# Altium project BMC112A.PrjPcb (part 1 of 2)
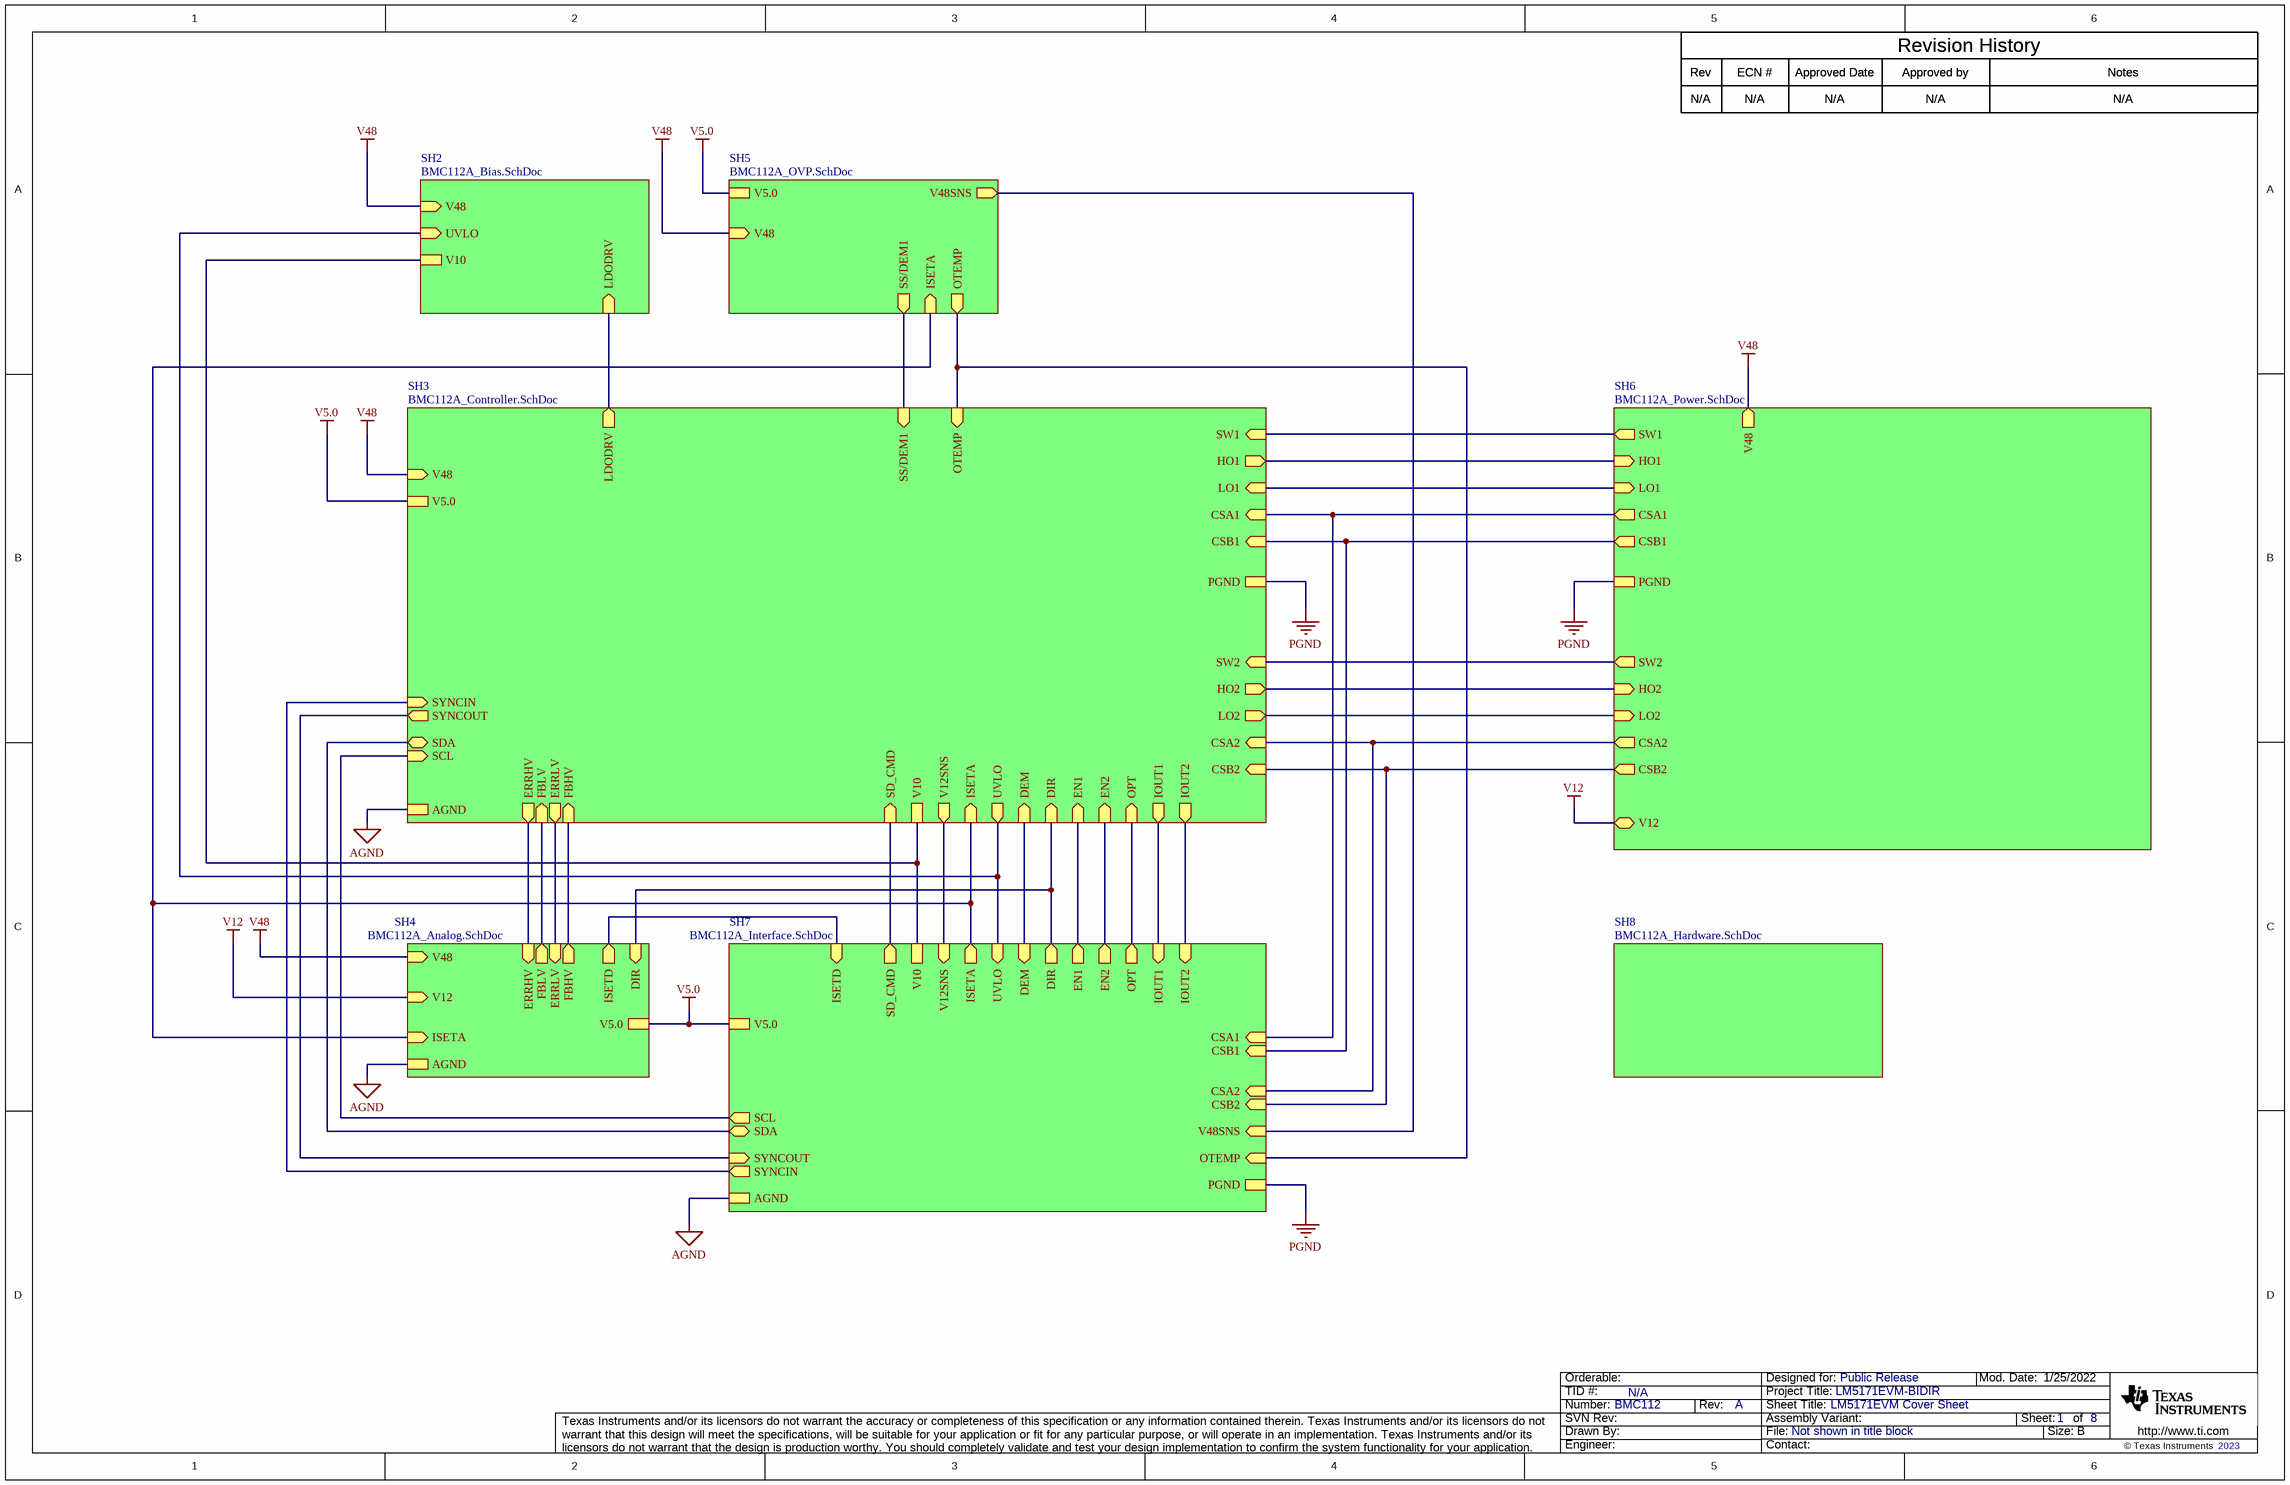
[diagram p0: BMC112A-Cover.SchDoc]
TID: N/A; SCH_Rev: A; PRJ_Title: LM5171EVM-BIDIR; PRJ_Number: BMC112; PRJ_Customer: Public Release; PCB_Rev: A; CopyrightYear: 2023
8 sheets, 367 parts. Net scope: hierarchical (ports join the sheet entries above them; power ports are global).
Board file: BMC112A.PcbDoc
Sheets:
  BMC112A-Cover.SchDoc
    SH2 = BMC112A_Bias.SchDoc
    SH5 = BMC112A_OVP.SchDoc
    SH3 = BMC112A_Controller.SchDoc
    SH6 = BMC112A_Power.SchDoc
    SH7 = BMC112A_Interface.SchDoc
    SH4 = BMC112A_Analog.SchDoc
    SH8 = BMC112A_Hardware.SchDoc

## Sheet BMC112A-Cover.SchDoc: LM5171EVM Cover Sheet
size 431 x 279 mm; Date: Not shown in title block; ApprovedBy: Not shown in title block; CheckedBy: Not shown in title block; Author: Not shown in title block; CompanyName: Not shown in title block; Engineer: Not shown in title block; Organization: Not shown in title block; Address1: Not shown in title block; Address2: Not shown in title block; Address3: Not shown in title block; Address4: Not shown in title block; DocumentNumber: 1; Revision: Use project parameter SCH_Rev; SheetNumber: 1; SheetTotal: 8; PageSetup: Record=PageOptions¦CenterHorizontal=True¦CenterVertical=True¦PrintScale=1.00¦XCorrection=1.00¦YCorrection=1.00¦PrintKind=0¦BorderSize=5000000¦LeftOffset=0¦BottomOffset=0¦Orientation=2¦PaperLength=1000¦PaperWidth=1000¦Scale=100¦PaperSource=15¦PrintQuality=600¦MediaType=1¦DitherType=10¦PaperKind=Letter¦PrintScaleMode=1

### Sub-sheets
SH2 = BMC112A_Bias.SchDoc: LDODRV (in), UVLO (in), V10, V48 (in)
SH3 = BMC112A_Controller.SchDoc: HO2 (out), CSA1 (in), CSB2 (in), CSA2 (in), IOUT1 (out), ERRLV (out), UVLO (out), V12SNS (out), SYNCIN (in), SYNCOUT (out), OTEMP (in), SW1 (in), FBHV (in), LO2 (out), OPT (in), FBLV (in), CSB1 (in), SW2 (in), ISETA (in), V10, EN1 (in), DIR (in), HO1 (out), ERRHV (out), LO1 (in), SDA (bidir), SD_CMD (in), IOUT2 (out), SS/DEM1 (in), EN2 (in), DEM (in), V48 (in), SCL (in), AGND, PGND, LDODRV (out), V5.0
SH4 = BMC112A_Analog.SchDoc: AGND, ISETA (in), ERRHV (in), DIR (in), V5.0, ERRLV (in), FBLV (out), ISETD (out), FBHV (out), V48 (in), V12 (in)
SH5 = BMC112A_OVP.SchDoc: V5.0, SS/DEM1 (out), ISETA (in), V48SNS (out), V48 (in), OTEMP (out)
SH6 = BMC112A_Power.SchDoc: CSA1 (out), CSA2 (out), LO1 (in), HO1 (in), CSB1 (out), SW1 (out), LO2 (in), CSB2 (out), SW2 (out), V12 (bidir), PGND, V48 (out), HO2 (in)
SH7 = BMC112A_Interface.SchDoc: IOUT2 (in), CSA1 (in), V48SNS (in), ISETD (in), V10, UVLO (in), SDA (bidir), DIR (out), DEM (in), SCL (out), IOUT1 (in), PGND, EN1 (out), V5.0, EN2 (out), SYNCOUT (in), SYNCIN (out), V12SNS (in), ISETA (out), SD_CMD (out), CSB2 (in), AGND, CSA2 (in), CSB1 (in), OPT (out), OTEMP (in)
SH8 = BMC112A_Hardware.SchDoc: no entries

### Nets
AGND: sheet SH3/AGND, sheet SH7/AGND, sheet SH4/AGND
PGND: sheet SH3/PGND, sheet SH6/PGND, sheet SH7/PGND
V5.0: sheet SH5/V5.0, sheet SH3/V5.0, sheet SH7/V5.0, sheet SH4/V5.0
V10: sheet SH2/V10, sheet SH3/V10, sheet SH7/V10
V12: sheet SH6/V12, sheet SH4/V12
V48: sheet SH2/V48, sheet SH5/V48, sheet SH3/V48, sheet SH6/V48, sheet SH4/V48
CSA1: sheet SH3/CSA1, sheet SH6/CSA1, sheet SH7/CSA1
CSA2: sheet SH3/CSA2, sheet SH6/CSA2, sheet SH7/CSA2
CSB1: sheet SH3/CSB1, sheet SH6/CSB1, sheet SH7/CSB1
CSB2: sheet SH3/CSB2, sheet SH6/CSB2, sheet SH7/CSB2
DEM: sheet SH3/DEM, sheet SH7/DEM
DIR: sheet SH3/DIR, sheet SH7/DIR, sheet SH4/DIR
EN1: sheet SH3/EN1, sheet SH7/EN1
EN2: sheet SH3/EN2, sheet SH7/EN2
ERRHV: sheet SH3/ERRHV, sheet SH4/ERRHV
ERRLV: sheet SH3/ERRLV, sheet SH4/ERRLV
FBHV: sheet SH3/FBHV, sheet SH4/FBHV
FBLV: sheet SH3/FBLV, sheet SH4/FBLV
HO1: sheet SH3/HO1, sheet SH6/HO1
HO2: sheet SH3/HO2, sheet SH6/HO2
IOUT1: sheet SH3/IOUT1, sheet SH7/IOUT1
IOUT2: sheet SH3/IOUT2, sheet SH7/IOUT2
ISETA: sheet SH5/ISETA, sheet SH3/ISETA, sheet SH7/ISETA, sheet SH4/ISETA
ISETD: sheet SH7/ISETD, sheet SH4/ISETD
LDODRV: sheet SH2/LDODRV, sheet SH3/LDODRV
LO1: sheet SH3/LO1, sheet SH6/LO1
LO2: sheet SH3/LO2, sheet SH6/LO2
OPT: sheet SH3/OPT, sheet SH7/OPT
OTEMP: sheet SH5/OTEMP, sheet SH3/OTEMP, sheet SH7/OTEMP
SCL: sheet SH3/SCL, sheet SH7/SCL
SD_CMD: sheet SH3/SD_CMD, sheet SH7/SD_CMD
SDA: sheet SH3/SDA, sheet SH7/SDA
SS/DEM1: sheet SH5/SS/DEM1, sheet SH3/SS/DEM1
SW1: sheet SH3/SW1, sheet SH6/SW1
SW2: sheet SH3/SW2, sheet SH6/SW2
SYNCIN: sheet SH3/SYNCIN, sheet SH7/SYNCIN
SYNCOUT: sheet SH3/SYNCOUT, sheet SH7/SYNCOUT
UVLO: sheet SH2/UVLO, sheet SH3/UVLO, sheet SH7/UVLO
V12SNS: sheet SH3/V12SNS, sheet SH7/V12SNS
V48SNS: sheet SH5/V48SNS, sheet SH7/V48SNS

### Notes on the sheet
- Rev
- N/A
- ECN #
- Approved Date
- Approved by
- Revision History
- Notes

## Sheet BMC112A_Bias.SchDoc: LM5171 EVM Auz Bias
size 431 x 279 mm; Date: Not shown in title block; ApprovedBy: Not shown in title block; CheckedBy: Not shown in title block; Author: Not shown in title block; CompanyName: Not shown in title block; Engineer: Not shown in title block; Organization: Not shown in title block; Address1: Not shown in title block; Address2: Not shown in title block; Address3: Not shown in title block; Address4: Not shown in title block; DocumentNumber: 5; Revision: Use project parameter SCH_Rev; SheetNumber: 2; SheetTotal: 8; PageSetup: Record=PageOptions¦CenterHorizontal=True¦CenterVertical=True¦PrintScale=1.00¦XCorrection=1.00¦YCorrection=1.00¦PrintKind=0¦BorderSize=5000000¦LeftOffset=0¦BottomOffset=0¦Orientation=2¦PaperLength=1000¦PaperWidth=1000¦Scale=100¦PaperSource=15¦PrintQuality=600¦MediaType=1¦DitherType=10¦PaperKind=Letter¦PrintScaleMode=1
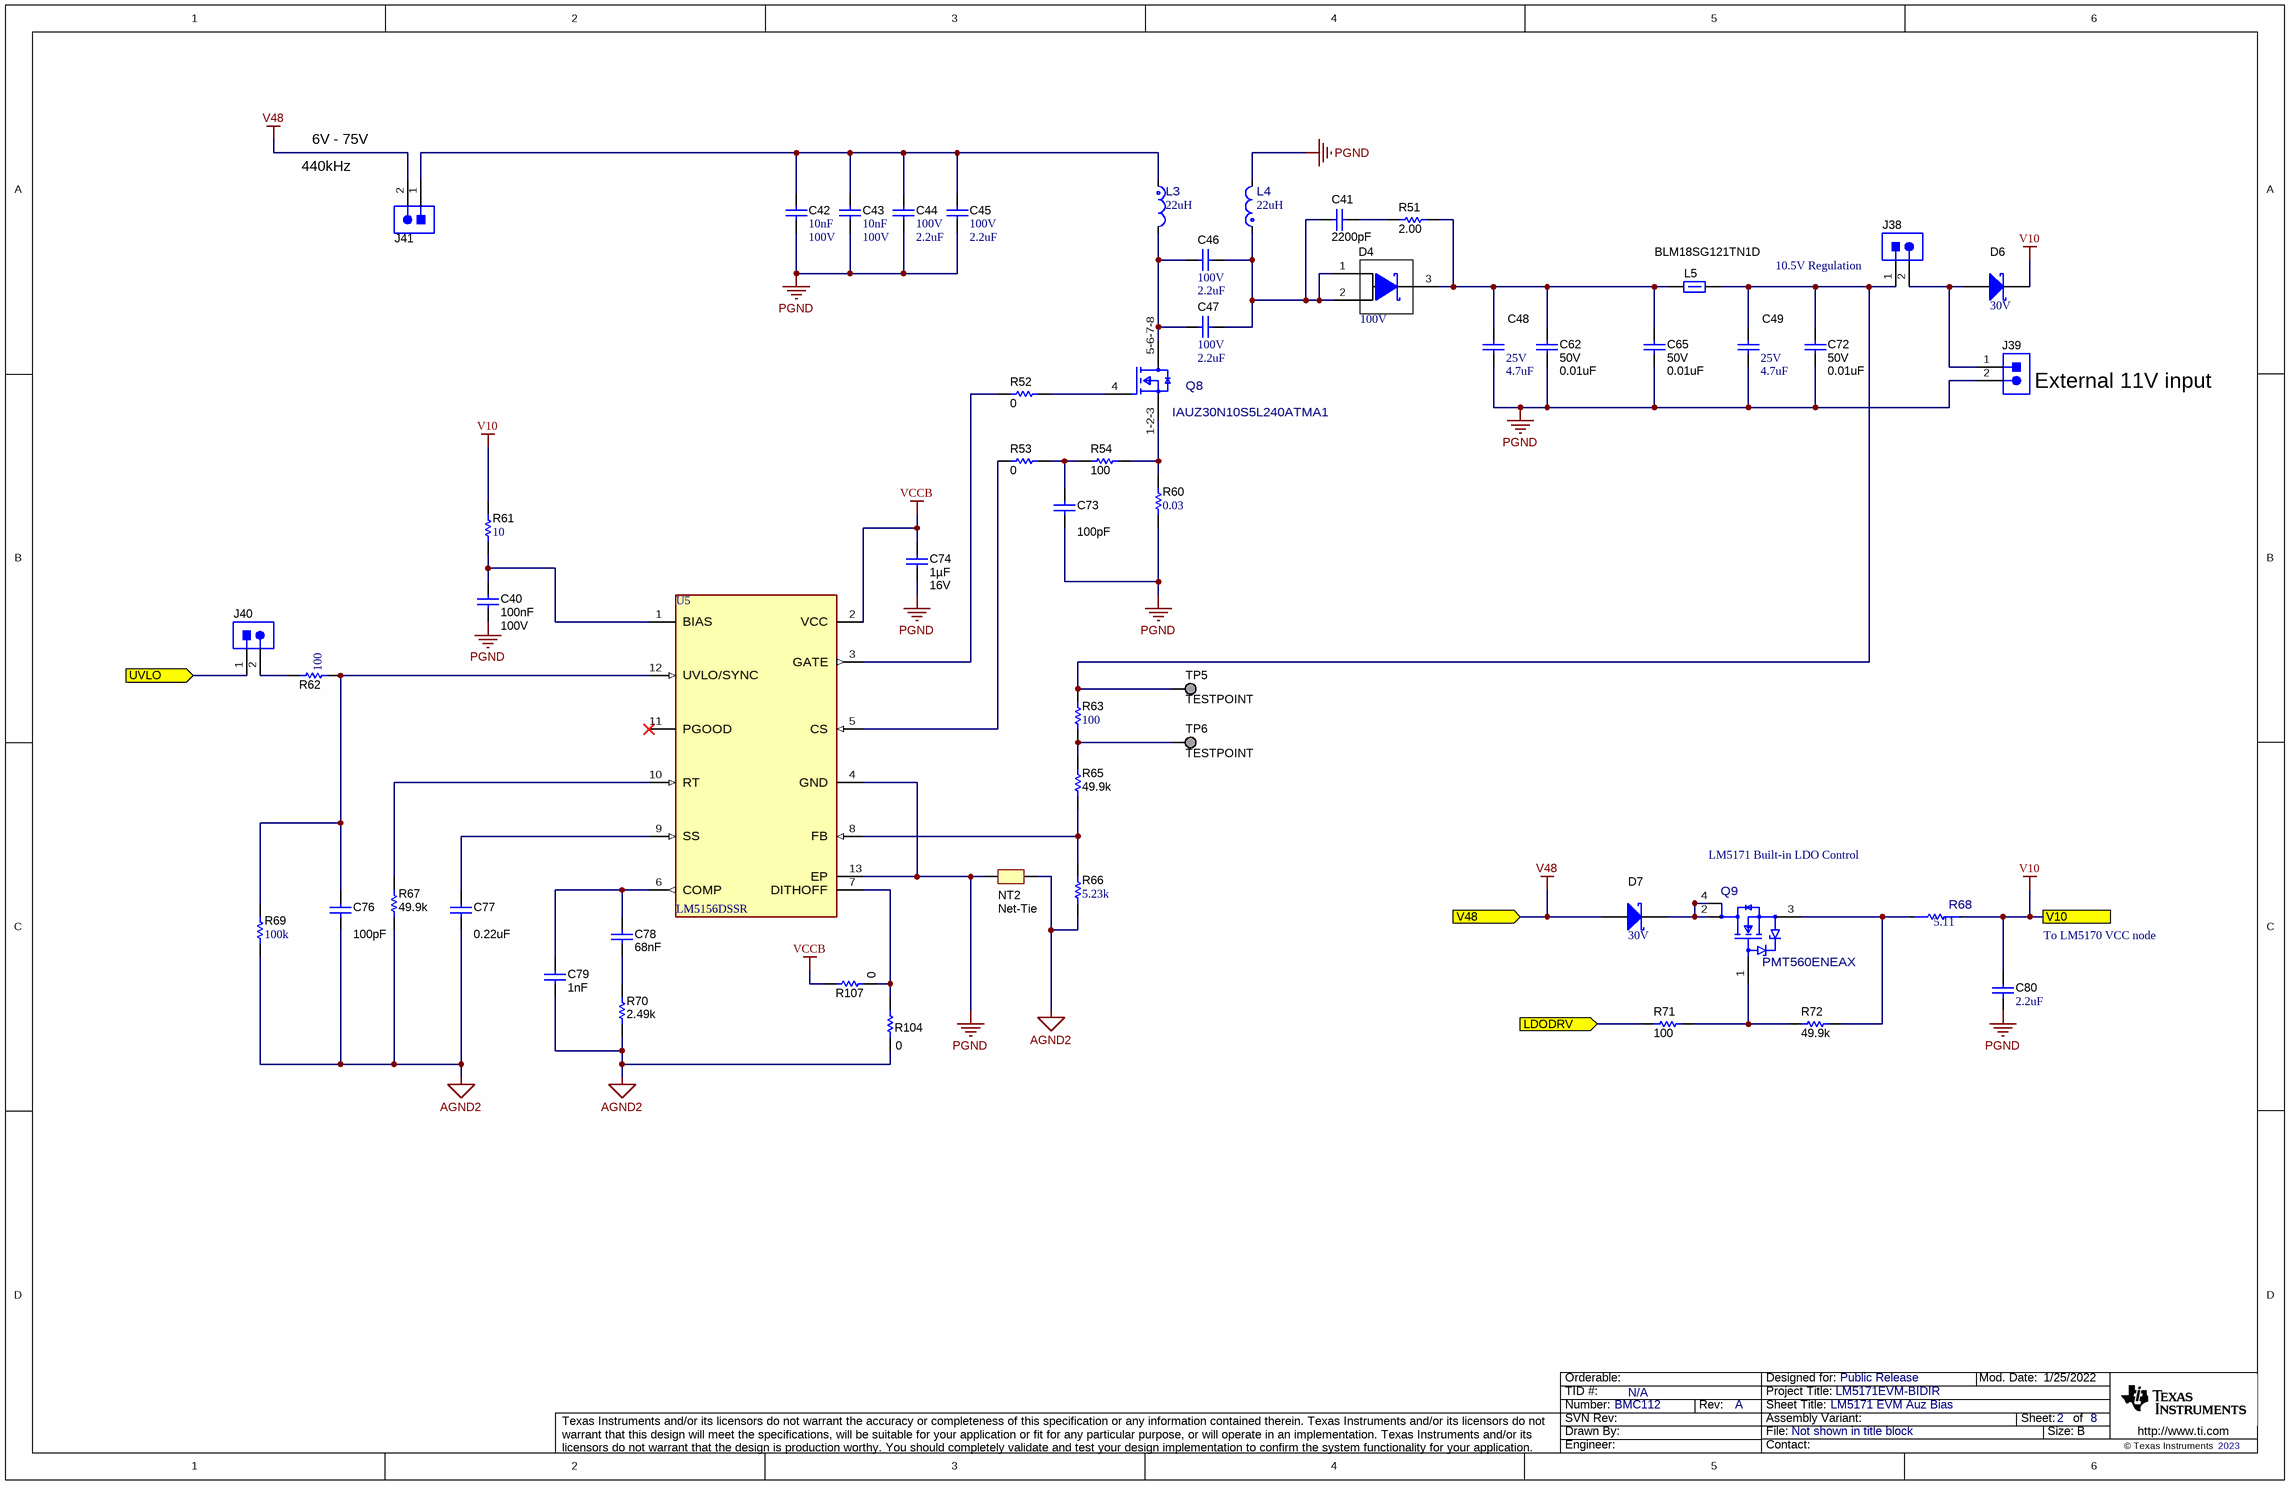
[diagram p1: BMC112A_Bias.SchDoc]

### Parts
C40  Cap_F: 100nF  VDC_V: 100V  [0603L]  (hidden comment: GCJ188R72A104KA01D)
C41  ValueDisplayed: 2200pF  [0603L]  (hidden comment: GRM188R72A222KA01D)
C42  Cap_F: 10nF  VDC_V: 100V  [0603L]  (hidden comment: GRM188R72A103KA01D)
C43  Cap_F: 10nF  VDC_V: 100V  [0603L]  (hidden comment: GRM188R72A103KA01D)
C44  VDC_V: 100V  ValueDisplayed: 2.2uF  [1206_180]  (hidden comment: C3216X7S2A225K160AB)
C45  VDC_V: 100V  ValueDisplayed: 2.2uF  [1206_180]  (hidden comment: C3216X7S2A225K160AB)
C46  VDC_V: 100V  ValueDisplayed: 2.2uF  [1206_180]  (hidden comment: C3216X7S2A225K160AB)
C47  VDC_V: 100V  ValueDisplayed: 2.2uF  [1206_180]  (hidden comment: C3216X7S2A225K160AB)
C48  VDC_V: 25V  ValueDisplayed: 4.7uF  [0805L]  (hidden comment: C0805C475K3PACTU)
C49  VDC_V: 25V  ValueDisplayed: 4.7uF  [0805L]  (hidden comment: C0805C475K3PACTU)
C62  VDC_V: 50V  ValueDisplayed: 0.01uF  [0402L]  (hidden comment: GRM155R71H103KA88D)
C65  VDC_V: 50V  ValueDisplayed: 0.01uF  [0402L]  (hidden comment: GRM155R71H103KA88D)
C72  VDC_V: 50V  ValueDisplayed: 0.01uF  [0402L]  (hidden comment: GRM155R71H103KA88D)
C73  ValueDisplayed: 100pF  [0603L]  (hidden comment: C0603C101F5GACTU)
C74  Cap_F: 1µF  VDC_V: 16V  [0603L]  (hidden comment: CGA3E1X7R1C105K080AC)
C76  ValueDisplayed: 100pF  [0603L]  (hidden comment: C0603C101F5GACTU)
C77  ValueDisplayed: 0.22uF  [0603L]  (hidden comment: CGA3E3X7R1H224K080AB)
C78  Cap_F: 68nF  [0603L]  (hidden comment: CGA3E2X7R1H683K080AA)
C79  Cap_F: 1nF  [0603L]  (hidden comment: C0603C102J5RACAUTO)
C80  ValueDisplayed: 2.2uF  [0805L]  (hidden comment: C2012X7R1C225K125AB)
D4  value 100V  [POWERDI5]  (hidden comment: PDS5100HQ-13)
D6  value 30V  [SMA]  (hidden comment: B230A-13-F)
D7  value 30V  [SMA]  (hidden comment: B230A-13-F)
J38  61300211121  [WURTH_61300211121]  (value not drawn)
J39  61300211121  [WURTH_61300211121]  (value not drawn)
J40  61300211121  [WURTH_61300211121]  (value not drawn)
J41  61300211121  [WURTH_61300211121]  (value not drawn)
L3  value 22uH  [FP-XGL6060-223MEC_SMT2_6MM51_6MM71-MFG]  (hidden comment: XGL6060-223MEC)
L4  value 22uH  [FP-XGL6060-223MEC_SMT2_6MM51_6MM71-MFG]  (hidden comment: XGL6060-223MEC)
L5  BLM18SG121TN1D  [0603]
NT2  Net-Tie  [Net-Tie_10mil]  (net tie, no BOM)
Q8  IAUZ30N10S5L240ATMA1  [FP-IAUZ30N10S5L240ATMA1_TDSON8-MFG]
Q9  PMT560ENEAX  [FP-PMT560ENEAX_SOT223-MFG]
R51  ValueDisplayed: 2.00  [1210]  (hidden comment: ERJ-14BQF2R0U)
R52  ValueDisplayed: 0  [0603L]  (hidden comment: RC0603JR-070RL)
R53  ValueDisplayed: 0  [0603L]  (hidden comment: RC0603JR-070RL)
R54  ValueDisplayed: 100  [0603L]  (hidden comment: RC0603FR-07100RL)
R60  ValueDisplayed: 0.03  [0612]  (hidden comment: PRL1632-R030-F-T1)
R61  ValueDisplayed: 10  [0805L]  (hidden comment: CRCW080510R0JNEA)
R62  ValueDisplayed: 100  [0603L]  (hidden comment: CRCW0603100RFKEA)
R63  ValueDisplayed: 100  [0603L]  (hidden comment: CRCW0603100RFKEA)
R65  ValueDisplayed: 49.9k  [0603L]  (hidden comment: RC0603FR-0749K9L)
R66  ValueDisplayed: 5.23k  [0603L]  (hidden comment: CRCW06035K23FKEA)
R67  ValueDisplayed: 49.9k  [0603L]  (hidden comment: RC0603FR-0749K9L)
R68  value 5.11  [FP-RCL06125R11FKEA_0612-MFG]  (hidden comment: RCL06125R11FKEA)
R69  ValueDisplayed: 100k  [0603L]  (hidden comment: CRCW0603100KFKEA)
R70  ValueDisplayed: 2.49k  [0603L]  (hidden comment: CRCW06032K49FKEA)
R71  ValueDisplayed: 100  [0603L]  (hidden comment: RC0603FR-07100RL)
R72  ValueDisplayed: 49.9k  [0603L]  (hidden comment: RC0603FR-0749K9L)
R104  ValueDisplayed: 0  [0603L]  (hidden comment: RC0603JR-070RL)
R107  ValueDisplayed: 0  [0603L]  (hidden comment: RC0603JR-070RL)
TP5  TESTPOINT  [TESTPOINT]  (no BOM)
TP6  TESTPOINT  [TESTPOINT]  (no BOM)
U5  LM5156DSSR  [DSS0012B]

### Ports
LDODRV (in), UVLO (in), V10, V48 (in)

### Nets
AGND2: C76.2 C77.2 C79.2 NT2.2 R66.1 R67.1 R69.1 R70.1 R104.2
PGND: C40.2 C42.2 C43.2 C44.1 C45.1 C48.1 C49.1 C62.2 C65.2 C72.2 C73.2 C74.1 C80.2 J39.2 L4.2 NT2.1 R60.1 U5.4(GND) U5.13(EP)
V10: C80.1 D6.1(K) R61.2 R68.1 ; port V10
V48: D7.2(A) J41.2 ; port V48
VCCB: C74.2 R107.1 U5.2(VCC)
LDODRV: R71.2 ; port LDODRV
UVLO: J40.1 ; port UVLO
NetC40_1: C40.1 R61.1 U5.1(BIAS)
NetC41_1: C41.1 R51.1
NetC41_2: C41.2 C46.2 C47.2 D4.1(A) D4.2(A) L4.1
NetC42_1: C42.1 C43.1 C44.2 C45.2 J41.1 L3.1
NetC46_1: C46.1 C47.1 L3.2 Q8.5-6-7-8(D)
NetC48_2: C48.2 C62.1 C65.1 D4.3(K) L5.2 R51.2
NetC49_2: C49.2 C72.1 J38.1 L5.1 R63.2 TP5.1
NetC73_1: C73.1 R53.1 R54.2
NetC76_1: C76.1 R62.1 R69.2 U5.12(UVLO/SYNC)
NetC77_1: C77.1 U5.9(SS)
NetC78_1: C78.1 C79.1 U5.6(COMP)
NetC78_2: C78.2 R70.2
NetD6_2: D6.2(A) J38.2 J39.1
NetD7_1: D7.1(K) Q9.2(D) Q9.4(D)
NetJ40_2: J40.2 R62.2
NetQ8_1-2-3: Q8.1-2-3(S) R54.1 R60.2
NetQ8_4: Q8.4(G) R52.1
NetQ9_1: Q9.1(G) R71.1 R72.2
NetQ9_3: Q9.3(S) R68.2 R72.1
NetR52_2: R52.2 U5.3(GATE)
NetR53_2: R53.2 U5.5(CS)
NetR63_1: R63.1 R65.2 TP6.1
NetR65_1: R65.1 R66.2 U5.8(FB)
NetR67_2: R67.2 U5.10(RT)
NetR104_1: R104.1 R107.2 U5.7(DITHOFF)

Not connected (* = marked no-connect by the designer): U5 11(PGOOD)*

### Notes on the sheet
- 440kHz
- 6V - 75V
- (near J38) 10.5V Regulation
- (near J39) External 11V input
- (near Q9) LM5171 Built-in LDO Control
- To LM5170 VCC node

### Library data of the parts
C40 = CMP-0064935-4: CAP, CERM, 0.1 uF, 100 V,+/- 10%, X7R, AEC-Q200 Grade 1, 0603; Manufacturer: MuRata; TaMin_C: -55°C; Polarized: N; SizeAreaWB_mm2: 4.68; Value1: Unknown; U/M: EA; Value: 0.1uF; TaMax_C: 125°C; SizeZ_mm: 1; SizeX_mm: 1.6; SizeY_mm: 0.8; Cap_Case: 0603; SizeArea_mm2: 1.28; AEC Qualified: Y; AEC Category: Q200
C41 = CMP-0007475-4: CAP, CERM, 2200 pF, 100 V, +/- 10%, X7R, 0603; Manufacturer: MuRata; Polarized: N; CompType: Capacitor; Value: 2200pF; U/M: EA; Cap_F: 2.2nF; Value1: Unknown; VDC_V: 100V; TaMin_C: -55°C; TaMax_C: 125°C; Cap_Case: 0603; SizeArea_mm2: 1.28; SizeAreaWB_mm2: 4.68; SizeX_mm: 1.6; SizeY_mm: 0.8; SizeZ_mm: 1; AEC Category: Q200
C42 C43 = CMP-0007468-5: CAP, CERM, 0.01 uF, 100 V, +/- 10%, X7R, 0603; Manufacturer: MuRata; TaMin_C: -55°C; Polarized: N; SizeAreaWB_mm2: 4.68; Value1: Unknown; U/M: EA; Value: 0.01uF; TaMax_C: 125°C; SizeZ_mm: 1; SizeX_mm: 1.6; SizeY_mm: 0.8; Cap_Case: 0603; SizeArea_mm2: 1.28; AEC Category: Q200
C44-C47 = CMP-0008724-2: CAP, CERM, 2.2 uF, 100 V, +/- 10%, X7S, 1206; Manufacturer: TDK; TaMin_C: -55°C; ESR_ohm: 5.718m; Polarized: N; SizeAreaWB_mm2: 10.92; Value1: 0.005718 ohm; U/M: EA; Value: 2.2uF; TaMax_C: 125°C; SizeZ_mm: 1.8; SizeX_mm: 3.2; SizeY_mm: 1.6; SizeArea_mm2: 5.12; Cap_F: 2.2µF; IRMS_A: 3.0363A; AEC Category: Q200
C48 C49 = CMP-0007800-2: CAP, CERM, 4.7 uF, 25 V, +/- 10%, X5R, 0805; Manufacturer: Kemet; TaMin_C: -55°C; Polarized: N; SizeAreaWB_mm2: 6.75; Value1: Unknown; U/M: EA; Value: 4.7uF; TaMax_C: 85°C; SizeZ_mm: 1.45; SizeX_mm: 2; SizeY_mm: 1.25; Cap_Case: 0805; SizeArea_mm2: 2.5; Cap_F: 4.7µF; AEC Category: Q200
C62 C65 C72 = CMP-0006674-2: CAP, CERM, 0.01 uF, 50 V, +/- 10%, X7R, 0402; Manufacturer: MuRata; TaMin_C: -55°C; Polarized: N; SizeAreaWB_mm2: 3; Value1: Unknown; U/M: EA; Value: 0.01uF; TaMax_C: 125°C; SizeZ_mm: 0.6; SizeX_mm: 1; SizeY_mm: 0.5; Cap_Case: 0402; Cap_F: 10nF; AEC Category: Q200
C73 = CMP-0080091-1: CAP, CERM, 100 pF, 50 V,+/- 1%, C0G/NP0, 0603; Manufacturer: Kemet; TaMin_C: -55°C; Polarized: N; SizeAreaWB_mm2: 4.68; U/M: EA; Value: 100pF; TaMax_C: 125°C; SizeZ_mm: 1; SizeX_mm: 1.6; Cap_Case: 0603; Value2: 50V; SizeArea_mm2: 1.28; CompType: Capacitor; AEC Category: Q200; SizeY_mm: 0.8; Green_REACh: Passed; Green_Lifecycle: Active
C74 = CMP-0079607-1: CAP, CERM, 1 µF, 16 V,+/- 10%, X7R, AEC-Q200 Grade 1, 0603; Manufacturer: TDK; TaMin_C: -55°C; Polarized: N; SizeAreaWB_mm2: 4.68; U/M: EA; Value: 1uF; TaMax_C: 125°C; SizeZ_mm: 1; SizeX_mm: 1.6; SizeY_mm: 0.8; Cap_Case: 0603; SizeArea_mm2: 1.28; AEC Qualified: Y; AEC Category: Q200
C76 = CMP-0080091-1: CAP, CERM, 100 pF, 50 V,+/- 1%, C0G/NP0, 0603; Manufacturer: Kemet; TaMin_C: -55°C; Polarized: N; SizeAreaWB_mm2: 4.68; U/M: EA; Value: 100pF; TaMax_C: 125°C; SizeZ_mm: 1; SizeX_mm: 1.6; SizeY_mm: 0.8; Cap_Case: 0603; Value2: 50V; SizeArea_mm2: 1.28; CompType: Capacitor; AEC Category: Q200; Green_REACh: Passed; Green_Lifecycle: Active
C77 = CMP-0007094-5: CAP, CERM, 0.22 uF, 50 V, +/- 10%, X7R, AEC-Q200 Grade 1, 0603; Manufacturer: TDK; TaMin_C: -55°C; ESR_ohm: 0.021699; Polarized: N; SizeAreaWB_mm2: 4.68; Value1: 0.021699 ohm; U/M: EA; Value: 0.22uF; TaMax_C: 125°C; SizeZ_mm: 1; SizeX_mm: 1.6; SizeY_mm: 0.8; Cap_Case: 0603; Value2: 50V; SizeArea_mm2: 1.28; CompType: Capacitor; AEC Qualified: Y; Cap_F: 220nF; IRMS_A: 1.12496A; AEC Category: Q200
C78 = CMP-0007080-5: CAP, CERM, 0.068 uF, 50 V, +/- 10%, X7R, AEC-Q200 Grade 1, 0603; Manufacturer: TDK; TaMin_C: -55°C; Polarized: N; SizeAreaWB_mm2: 4.68; Value1: 0.035979 ohm; U/M: EA; TaMax_C: 125°C; SizeZ_mm: 1; SizeX_mm: 1.6; SizeY_mm: 0.8; Cap_Case: 0603; Value2: 50V; SizeArea_mm2: 1.28; AEC Qualified: Y; AEC Category: Q200; ESR_ohm: 0.035979; IRMS_A: 886.483mA
C79 = CMP-0006844-4: CAP, CERM, 1000 pF, 50 V, +/- 5%, X7R, AEC-Q200 Grade 1, 0603; Manufacturer: Kemet; TaMin_C: -55°C; Polarized: N; SizeAreaWB_mm2: 4.68; Value1: Unknown; U/M: EA; Value: 1000pF; TaMax_C: 125°C; SizeZ_mm: 1; SizeX_mm: 1.6; SizeY_mm: 0.8; Cap_Case: 0603; Value2: 50V; SizeArea_mm2: 1.28; AEC Qualified: Y; AEC Category: Q200
C80 = CMP-0007867-2: CAP, CERM, 2.2 uF, 16 V, +/- 10%, X7R, 0805; Manufacturer: TDK; Value: 2.2uF; U/M: EA; VDC_V: 16V; Polarized: N; Cap_F: 2.2µF; ESR_ohm: 4.9m; Value1: 0.0049 ohm; TaMin_C: -55°C; TaMax_C: 125°C; Cap_Case: 0805; AEC Category: Q200; SizeArea_mm2: 2.5; SizeAreaWB_mm2: 6.75; SizeX_mm: 2; SizeY_mm: 1.25; SizeZ_mm: 1.45
D4 = CMP-0080010-2: Diode, Schottky, 100 V, 5 A, AEC-Q101, PowerDI5; Manufacturer: Diodes Inc.; Io_A: 5A; SizeAreaWB_mm2: 49.56; TJmax_C: 175°C; SizeZ_mm: 1.05; SizeX_mm: 6.4; SizeY_mm: 3.9; Vf_V: 710mV; Value2: 0.71V; SizeArea_mm2: 24.96; AEC Qualified: Y; AEC Category: Q101; RJC_CperW: 5
D6 D7 = CMP-0028401-2: Diode, Schottky, 30 V, 2 A, SMA; Manufacturer: Diodes Inc.; Io_A: 2A; Green_Lifecycle: Active; SizeAreaWB_mm2: 37.3428; Green_REACh: Passed; TJmax_C: 150°C; SizeZ_mm: 2.87; SizeX_mm: 5.59; SizeY_mm: 2.92; Vf_V: 500mV; Value2: 0.5V; SizeArea_mm2: 16.3228; AEC Category: Q101; RJC_CperW: 20
J38-J41 = CMP-0054794-2: Header, 2.54 mm, 2x1, Gold, TH; Manufacturer: Wurth Elektronik; Green_REACh: Passed; Green_Lifecycle: Active; Cert_UL: Y; Gender: Male; Pitch_mm: 2.54; Row_Count: 1; Shrouded: N
L3 L4 = CMP-0095453-1: 22 µH Shielded Inductor 5.8 A 46.9mOhm Max Nonstandard; Manufacturer: Coilcraft; Isat: 2.5A; Test Frequency: 1MHz; SizeZ_mm: 6.1mm; Self Resonant Frequency: 9MHz; Irms: 5.8A; DCR_ohm: 46.9m; Ind_H: 22µH; Material: Composite; AEC Qualified: Yes; AEC Grade: Grade 1; TaMax_C: +125°C; Tolerance_%: 20%; Shrouded: true; TaMin_C: -40°C
L5 = CMP-0003352-2: Ferrite Bead, 120 ohm @ 100 MHz, 3 A, 0603; Manufacturer: MuRata; ZTyp@100MHz_Ohm: 120; SizeAreaWB_mm2: 4.68; DCR_ohm: 0.025; Value1: 0.025 ohm; Value: 120 ohm; Imax_A: 3A; SizeZ_mm: 1; SizeX_mm: 1.6; SizeY_mm: 0.8; SizeArea_mm2: 1.28
NT2 = CMP-0078142-6: Single point connection between nets.
Q8 = CMP-0093385-1: N-Channel 100 V 30A (Tc) 45.5W (Tc) Surface Mount PG-TSDSON-8-32; Manufacturer: Infineon; SizeZ_mm: 1.05mm; VdsMax_V: 1.1V; Vgs_V: 20V; AEC Qualified: Yes; QgTyp_nC: 9.5nC @ 10V; Rdson45_ohm: 19.5m; ChMode: False; Input Capacitace At Vds: 640pF @ 50V; Pulse Drain Current: 120A; Rthja Max: 62K/W; Standoff Height: 0mm; Number Of Channels: 1; Threshold Vgs Max: 2.2V; Reverse Recovery Time: 37ns; Turn On Delay Time: 2ns; Typ Forward Diode Voltage: 0.9V; Threshold Vgs Min: 1.2V; Drain To Source Breakdown Voltage: 100V; Reverse Recovery Charge: 34nC; TJmax_C: +175°C; Turn Off Delay Time: 4.6ns; AEC Grade: Grade 0
Q9 = CMP-0096318-1: Small Signal low RDSon automotive Trans MOSFET N-CH 100V 1.1A 3-Pin SC-73 T/R; Manufacturer: Nexperia; Transconductance: 3.5S; ChMode: False; SizeZ_mm: 1.8mm; QgTyp_nC: 2.9nC @ 10V; Rthja Max: 145K/W; TJmax_C: +150°C; AEC Grade: Grade 0; Power_W: 750mW; Typ Forward Diode Voltage: 0.9V; Turn Off Delay Time: 10ns; TaMin_C: -55°C; Input Capacitace At Vds: 112pF @ 50V; VdsMax_V: 1.2V; Vgs_V: 20V; Threshold Vgs Max: 2.7V; Threshold Vgs Min: 1.3V; AEC Qualified: Yes; Standoff Height: 0.01mm; Turn On Delay Time: 6ns; Number Of N Channels: 1; Rdson45_ohm: 0.527; Pulse Drain Current: 4.4A
R51 = CMP-0015029-2: RES, 2.00, 1%, 0.5 W, AEC-Q200 Grade 0, 1210; Manufacturer: Panasonic; Power_W: 500mW; TempCo: 100 ppm/C; SizeAreaWB_mm2: 14.7; Value_Code: 2R00; U/M: EA; Value: 2.00; EIA_Code: E96; Res_ohm: 2; SizeX_mm: 3.2; SizeY_mm: 2.5; SizeZ_mm: 1.35; Value2: 0.5W; SizeArea_mm2: 8; AEC Qualified: Y; AEC Grade: 0; AEC Category: Q200
R52 R53 R104 R107 = CMP-0025885-5: RES, 0, 5%, 0.1 W, 0603; Manufacturer: Yageo; Power_W: 100mW; TempCo: 200 ppm/C; Value_Code: 0000; Value: 0; EIA_Code: E24; SizeX_mm: 1.6; SizeY_mm: 0.8; SizeZ_mm: 1; Value2: 0.1W; SizeArea_mm2: 1.28; AEC Qualified: N; VDC_V: 75V; AEC Category: Q200; SizeAreaWB_mm2: 4.68
R54 R71 = CMP-0022736-4: RES, 100, 1%, 0.1 W, 0603; Manufacturer: Yageo; Power_W: 100mW; TempCo: 100 ppm/C; Value_Code: 100R; Value: 100; EIA_Code: E96; SizeX_mm: 1.6; SizeY_mm: 0.8; SizeZ_mm: 1; Value2: 0.1W; SizeArea_mm2: 1.28; AEC Qualified: N; VDC_V: 75V; AEC Category: Q200; SizeAreaWB_mm2: 4.68
R60 = CMP-0015219-3: RES, 0.03, 1%, 1 W, 0612; Manufacturer: Susumu Co Ltd; SizeArea_mm2: 5.12; U/M: EA; Value2: 1W; Value_Code: R030; Value: 0.03; EIA_Code: E96; AEC Category: Q200; SizeAreaWB_mm2: 10.92; Res_ohm: 30m; SizeZ_mm: 0.85; SizeY_mm: 3.2; SizeX_mm: 1.6; TempCo: 100 ppm/C
R61 = CMP-0020448-3: RES, 10, 5%, 0.125 W, AEC-Q200 Grade 0, 0805; Manufacturer: Vishay-Dale; Power_W: 125mW; TempCo: 200 ppm/C; Value_Code: 10R0; Value: 10; EIA_Code: E24; SizeX_mm: 2; SizeY_mm: 1.25; SizeZ_mm: 1.45; Value2: 0.125W; SizeArea_mm2: 2.5; AEC Qualified: Y; VDC_V: 150V; AEC Category: Q200; AEC Grade: 0
R62 R63 = CMP-0021991-4: RES, 100, 1%, 0.1 W, AEC-Q200 Grade 0, 0603; Manufacturer: Vishay-Dale; Power_W: 100mW; TempCo: 100 ppm/C; Value_Code: 100R; Value: 100; EIA_Code: E96; SizeX_mm: 1.6; SizeY_mm: 0.8; SizeZ_mm: 1; Value2: 0.1W; SizeArea_mm2: 1.28; AEC Qualified: Y; VDC_V: 75V; AEC Category: Q200; AEC Grade: 0
R65 R67 R72 = CMP-0023142-5: RES, 49.9 k, 1%, 0.1 W, 0603; Manufacturer: Yageo; Power_W: 100mW; TempCo: 100 ppm/C; Value_Code: 49k9; Value: 49.9k; EIA_Code: E96; SizeX_mm: 1.6; SizeY_mm: 0.8; SizeZ_mm: 1; Value2: 0.1W; SizeArea_mm2: 1.28; AEC Qualified: N; VDC_V: 75V; AEC Category: Q200; SizeAreaWB_mm2: 4.68
R66 = CMP-0022510-4: RES, 5.23 k, 1%, 0.1 W, AEC-Q200 Grade 0, 0603; Manufacturer: Vishay-Dale; Power_W: 100mW; TempCo: 100 ppm/C; Value_Code: 5k23; Value: 5.23k; EIA_Code: E96; SizeX_mm: 1.6; SizeY_mm: 0.8; SizeZ_mm: 1; Value2: 0.1W; SizeArea_mm2: 1.28; AEC Qualified: Y; VDC_V: 75V; AEC Category: Q200; AEC Grade: 0
R68 = CMP-0096401-1: Res Thick Film 0612 5.11Ohm 1% 1/2W ±100ppm/K Molded Paper T/R; Manufacturer: Vishay Dale; AEC Grade: Grade 0; AEC Qualified: Yes; VDC_V: 200V; Power_W: 1W; SizeZ_mm: 0.65mm; TempCo: 100ppm/°C
R69 = CMP-0021990-4: RES, 100 k, 1%, 0.1 W, AEC-Q200 Grade 0, 0603; Manufacturer: Vishay-Dale; Power_W: 100mW; TempCo: 100 ppm/C; Value: 100k; EIA_Code: E96; SizeX_mm: 1.6; SizeY_mm: 0.8; SizeZ_mm: 1; Value2: 0.1W; SizeArea_mm2: 1.28; AEC Qualified: Y; VDC_V: 75V; AEC Category: Q200; AEC Grade: 0
R70 = CMP-0022277-4: RES, 2.49 k, 1%, 0.1 W, AEC-Q200 Grade 0, 0603; Manufacturer: Vishay-Dale; Power_W: 100mW; TempCo: 100 ppm/C; Value_Code: 2k49; Value: 2.49k; EIA_Code: E96; SizeX_mm: 1.6; SizeY_mm: 0.8; SizeZ_mm: 1; Value2: 0.1W; SizeArea_mm2: 1.28; AEC Qualified: Y; VDC_V: 75V; AEC Category: Q200; AEC Grade: 0
TP5 TP6 = CMP-0078143-4: TEST POINT.  No entry in BOM.
U5 = CMP-0860750-2: 2.2-MHz Wide VIN 65-V Non-synchronous Boost/SEPIC/Flyback Controller with Dual Random Spread Spectrum, DSS0012B (WSON-12); Alternate PartNumber: LM5156DSST; Alternate Manufacturer: Texas Instruments; SizeAreaWB_mm2: 12; SizeZ_mm: 0.8; CompType: IC; SizeX_mm: 2; AEC Category: Q200; SizeArea_mm2: 6; SizeY_mm: 3; AEC Qualified: N

## Sheet BMC112A_OVP.SchDoc: LM5171 EVM Over Temp Schematic
size 431 x 279 mm; Date: Not shown in title block; ApprovedBy: Not shown in title block; CheckedBy: Not shown in title block; Author: Not shown in title block; CompanyName: Not shown in title block; Engineer: Not shown in title block; Organization: Not shown in title block; Address1: Not shown in title block; Address2: Not shown in title block; Address3: Not shown in title block; Address4: Not shown in title block; DocumentNumber: 7; Revision: Use project parameter SCH_Rev; SheetNumber: 5; SheetTotal: 8; PageSetup: Record=PageOptions¦CenterHorizontal=True¦CenterVertical=True¦PrintScale=1.00¦XCorrection=1.00¦YCorrection=1.00¦PrintKind=0¦BorderSize=5000000¦LeftOffset=0¦BottomOffset=0¦Orientation=2¦PaperLength=1000¦PaperWidth=1000¦Scale=100¦PaperSource=15¦PrintQuality=600¦MediaType=1¦DitherType=10¦PaperKind=Letter¦PrintScaleMode=1
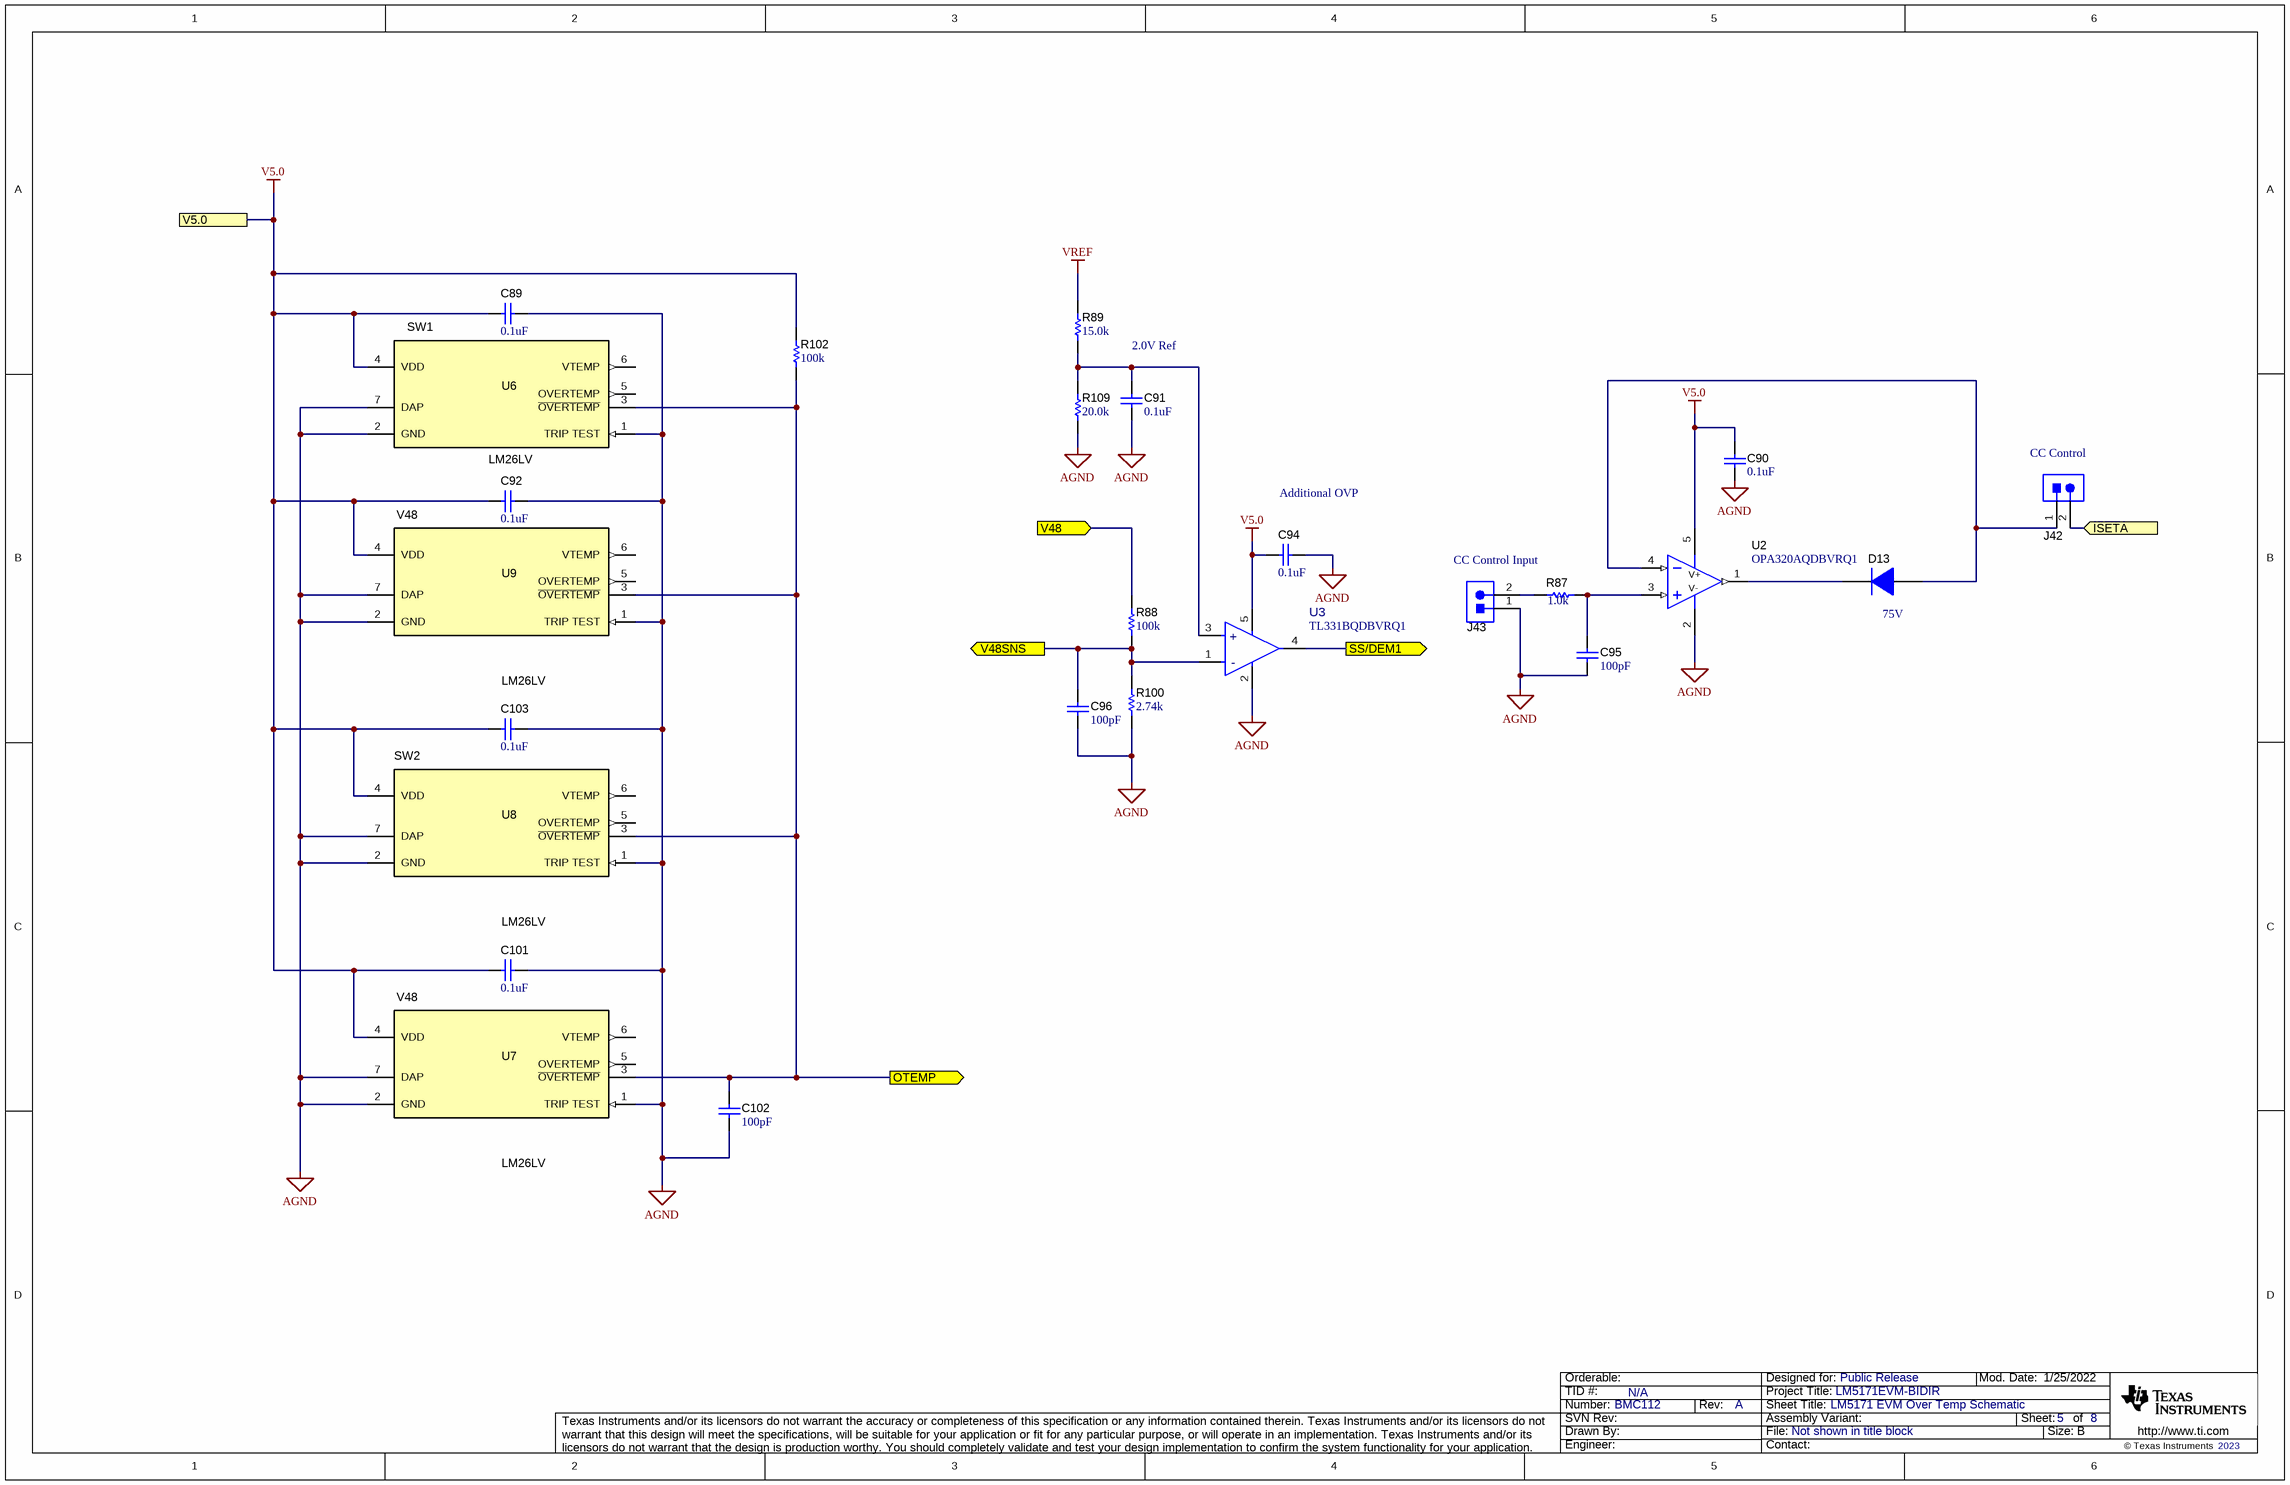
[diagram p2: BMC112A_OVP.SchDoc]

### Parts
C89  ValueDisplayed: 0.1uF  [0603L]  (hidden comment: GRM188R72A104KA35D)
C90  ValueDisplayed: 0.1uF  [0603L]  (hidden comment: GRM188R72A104KA35D)
C91  ValueDisplayed: 0.1uF  [0603L]  (hidden comment: GRM188R72A104KA35D)
C92  ValueDisplayed: 0.1uF  [0603L]  (hidden comment: GRM188R72A104KA35D)
C94  ValueDisplayed: 0.1uF  [0603L]  (hidden comment: GRM188R72A104KA35D)
C95  ValueDisplayed: 100pF  [0603L]  (hidden comment: C0603C101J5GACTU)
C96  ValueDisplayed: 100pF  [0603L]  (hidden comment: C0603C101J5GACTU)
C101  ValueDisplayed: 0.1uF  [0603L]  (hidden comment: GRM188R72A104KA35D)
C102  ValueDisplayed: 100pF  [0603L]  (hidden comment: C0603C101J5GACTU)
C103  ValueDisplayed: 0.1uF  [0603L]  (hidden comment: GRM188R72A104KA35D)
D13  value 75V  [SOD-323]  (hidden comment: 1N4448WX-TP)
J42  61300211121  [WURTH_61300211121]  (value not drawn)
J43  61300211121  [WURTH_61300211121]  (value not drawn)
R87  ValueDisplayed: 1.0k  [0603L]  (hidden comment: CRCW06031K00JNEA)
R88  ValueDisplayed: 100k  [0805L]  (hidden comment: CRCW0805100KFKEA)
R89  ValueDisplayed: 15.0k  [0603L]  (hidden comment: CRCW060315K0FKEA)
R100  ValueDisplayed: 2.74k  [0603L]  (hidden comment: CRCW06032K74FKEA)
R102  ValueDisplayed: 100k  [0402L]  (hidden comment: CRCW0402100KFKED)
R109  ValueDisplayed: 20.0k  [0603L]  (hidden comment: CRCW060320K0FKEA)
U2  OPA320AQDBVRQ1  [DBV0005A_N]
U3  TL331BQDBVRQ1  [DBV0005A-MFG]
U6  LM26LV  [NGF0006A]
U7  LM26LV  [NGF0006A]
U8  LM26LV  [NGF0006A]
U9  LM26LV  [NGF0006A]

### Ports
ISETA (in), OTEMP (out), SS/DEM1 (out), V5.0, V48 (in), V48SNS (out)

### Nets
AGND: C89.2 C90.1 C91.2 C92.2 C94.1 C95.2 C96.2 C101.2 C102.2 C103.2 J43.1 R100.1 R109.1 U2.2(V-) U3.2(GND) U6.1(TRIP_TEST) U6.2(GND) U6.7(DAP) U7.1(TRIP_TEST) U7.2(GND) U7.7(DAP) U8.1(TRIP_TEST) U8.2(GND) U8.7(DAP) U9.1(TRIP_TEST) U9.2(GND) U9.7(DAP)
V5.0: C89.1 C90.2 C92.1 C94.2 C101.1 C103.1 R102.2 U2.5(V+) U3.5(VCC) U6.4(VDD) U7.4(VDD) U8.4(VDD) U9.4(VDD) ; port V5.0
V48: R88.2 ; port V48
VREF: R89.1
ISETA: J42.2 ; port ISETA
OTEMP: C102.1 R102.1 U6.3(~{OVERTEMP}) U7.3(~{OVERTEMP}) U8.3(~{OVERTEMP}) U9.3(~{OVERTEMP}) ; port OTEMP
SS/DEM1: U3.4(OUT) ; port SS/DEM1
V48SNS: C96.1 R88.1 R100.2 U3.1(IN-) ; port V48SNS
NetC91_1: C91.1 R89.2 R109.2 U3.3(IN+)
NetC95_1: C95.1 R87.1 U2.3(IN+)
NetD13_1: D13.1(K) U2.1(OUT)
NetD13_2: D13.2(A) J42.1 U2.4(IN-)
NetJ43_2: J43.2 R87.2

Not connected (* = marked no-connect by the designer): U6 5(OVERTEMP) 6(VTEMP); U7 5(OVERTEMP) 6(VTEMP); U8 5(OVERTEMP) 6(VTEMP); U9 5(OVERTEMP) 6(VTEMP)

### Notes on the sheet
- (near U6) SW1
- 2.0V Ref
- Additional OVP
- (near J42) CC Control
- (near U9) V48
- CC Control Input
- (near U8) SW2
- (near U7) V48

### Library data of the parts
C89-C92 C94 C101 C103 = CMP-0007469-4: CAP, CERM, 0.1 uF, 100 V, +/- 10%, X7R, 0603; Manufacturer: MuRata; Polarized: N; Value: 0.1uF; U/M: EA; Cap_F: 100nF; Value1: Unknown; VDC_V: 100V; TaMin_C: -55°C; TaMax_C: 125°C; Cap_Case: 0603; AEC Category: Q200; SizeArea_mm2: 1.28; SizeAreaWB_mm2: 4.68; SizeX_mm: 1.6; SizeY_mm: 0.8; SizeZ_mm: 1
C95 C96 C102 = CMP-0006841-4: CAP, CERM, 100 pF, 50 V, +/- 5%, C0G/NP0, 0603; Manufacturer: Kemet; Polarized: N; Value: 100pF; U/M: EA; Value1: Unknown; VDC_V: 50V; TaMin_C: -55°C; TaMax_C: 125°C; Cap_Case: 0603; AEC Category: Q200; SizeArea_mm2: 1.28; SizeAreaWB_mm2: 4.68; SizeX_mm: 1.6; SizeY_mm: 0.8; SizeZ_mm: 1
D13 = CMP-0076911-2: Diode, Switching, 75 V, 0.25 A, SOD-323; Manufacturer: Micro Commercial Components; Value1: 0.25A; Io_A: 250mA; TJmax_C: 150°C; AEC Category: Q101; Green_Lifecycle: Not Set; Green_REACh: Incomplete; SizeArea_mm2: 3.645; SizeAreaWB_mm2: 8.695; SizeX_mm: 2.7; SizeY_mm: 1.35; SizeZ_mm: 1.0
J42 J43 = CMP-0054794-2: Header, 2.54 mm, 2x1, Gold, TH; Manufacturer: Wurth Elektronik; Cert_UL: Y; Gender: Male; Green_Lifecycle: Active; Green_REACh: Passed; Pitch_mm: 2.54; Row_Count: 1; Shrouded: N
R87 = CMP-0025729-4: RES, 1.0 k, 5%, 0.1 W, AEC-Q200 Grade 0, 0603; Manufacturer: Vishay-Dale; Value: 1.0k; Res_ohm: 1k; Value_Code: 1k00; Power_W: 100mW; Value2: 0.1W; VDC_V: 75V; TempCo: 200 ppm/C; EIA_Code: E24; SizeX_mm: 1.6; SizeY_mm: 0.8; SizeZ_mm: 1; SizeArea_mm2: 1.28; AEC Qualified: Y; AEC Category: Q200; AEC Grade: 0
R88 = CMP-0020834-3: RES, 100 k, 1%, 0.125 W, AEC-Q200 Grade 0, 0805; Manufacturer: Vishay-Dale; Value: 100k; Power_W: 125mW; Value2: 0.125W; VDC_V: 150V; TempCo: 100 ppm/C; EIA_Code: E96; SizeX_mm: 2; SizeY_mm: 1.25; SizeZ_mm: 1.45; SizeArea_mm2: 2.5; AEC Qualified: Y; AEC Category: Q200; AEC Grade: 0
R89 = CMP-0022066-4: RES, 15.0 k, 1%, 0.1 W, AEC-Q200 Grade 0, 0603; Manufacturer: Vishay-Dale; Value: 15.0k; Res_ohm: 15k; Value_Code: 15k0; Power_W: 100mW; Value2: 0.1W; VDC_V: 75V; TempCo: 100 ppm/C; EIA_Code: E96; SizeX_mm: 1.6; SizeY_mm: 0.8; SizeZ_mm: 1; SizeArea_mm2: 1.28; AEC Qualified: Y; AEC Category: Q200; AEC Grade: 0
R100 = CMP-0022281-4: RES, 2.74 k, 1%, 0.1 W, AEC-Q200 Grade 0, 0603; Manufacturer: Vishay-Dale; Power_W: 100mW; TempCo: 100 ppm/C; Value_Code: 2k74; Value: 2.74k; EIA_Code: E96; SizeX_mm: 1.6; SizeY_mm: 0.8; SizeZ_mm: 1; Value2: 0.1W; SizeArea_mm2: 1.28; AEC Qualified: Y; VDC_V: 75V; AEC Category: Q200; AEC Grade: 0
R102 = CMP-0025950-3: RES, 100 k, 1%, 0.063 W, AEC-Q200 Grade 0, 0402; Manufacturer: Vishay-Dale; Value: 100k; Power_W: 63mW; Value2: 0.063W; VDC_V: 50V; TempCo: 100 ppm/C; EIA_Code: E96; AEC Category: Q200; AEC Grade: 0; AEC Qualified: Y; SizeArea_mm2: 0.5; SizeX_mm: 1; SizeZ_mm: 0.6
R109 = CMP-0022204-4: RES, 20.0 k, 1%, 0.1 W, AEC-Q200 Grade 0, 0603; Manufacturer: Vishay-Dale; Value: 20.0k; Res_ohm: 20k; Value_Code: 20k0; Power_W: 100mW; Value2: 0.1W; VDC_V: 75V; TempCo: 100 ppm/C; EIA_Code: E96; SizeArea_mm2: 1.28; SizeX_mm: 1.6; SizeY_mm: 0.8; SizeZ_mm: 1; AEC Category: Q200; AEC Qualified: Y; AEC Grade: 0
U2 = CMP-0077859-1: Automotive Qualified Precision, Zero-Crossover, 20MHz, 0.9pA Ib, RRIO, CMOS Operational Amplifier, DBV0005A (SOT-23-5); Alternate PartNumber: OPA320AQDBVTQ1; Alternate Manufacturer: Texas Instruments; SizeAreaWB_mm2: 14.82; SizeZ_mm: 1.45; SizeX_mm: 2.8; SizeY_mm: 2.9; SizeArea_mm2: 8.12; CompType: IC; AEC Qualified: Y; AEC Category: Q200
U3 = CMP-0089971-1: Automotive Catalog Single Differential Comparator 5-SOT-23 -40 to 125; Manufacturer: Texas Instruments; Max Supply Voltage: 36V; Output Current Per Channel: 20mA; SizeZ_mm: 1.45mm; Response Time: 1us; Number Of Channels: 1; AEC Grade: Grade 1; TaMin_C: -40°C; TJmax_C: +125°C; Standoff Height: 0mm; Min Supply Voltage: 3V; Input Bias Current: 0.0035uA; AEC Qualified: Yes; Nominal Supply Current: 210-275uA; Input Offset Voltage: 0.37mV
U6-U9 = CMP-0860728-1: 1.6V-Capable Temperature Sensor Switch with Factory Programmed Trip Points, NGF0006A (WSON-6); PartNumber: LM26LVCISD-145/NOPB; Manufacturer: Texas Instruments; CompType: IC; AEC Category: Q200; AEC Qualified: N; Green_Lifecycle: Active; Green_REACh: Passed; Rating: Catalog; SizeArea_mm2: 5.5; SizeAreaWB_mm2: 11.2; SizeX_mm: 2.5; SizeY_mm: 2.2; SizeZ_mm: 0.8

## Sheet BMC112A_Controller.SchDoc: LM5171EVM Contoller Schematic
size 431 x 279 mm; Date: Not shown in title block; ApprovedBy: Not shown in title block; CheckedBy: Not shown in title block; Author: Not shown in title block; CompanyName: Not shown in title block; Engineer: Not shown in title block; Organization: Not shown in title block; Address1: Not shown in title block; Address2: Not shown in title block; Address3: Not shown in title block; Address4: Not shown in title block; DocumentNumber: 2; Revision: Use project parameter SCH_Rev; SheetNumber: 3; SheetTotal: 8; PageSetup: Record=PageOptions¦CenterHorizontal=True¦CenterVertical=True¦PrintScale=1.00¦XCorrection=1.00¦YCorrection=1.00¦PrintKind=0¦BorderSize=5000000¦LeftOffset=0¦BottomOffset=0¦Orientation=2¦PaperLength=1000¦PaperWidth=1000¦Scale=100¦PaperSource=15¦PrintQuality=600¦MediaType=1¦DitherType=10¦PaperKind=Letter¦PrintScaleMode=1
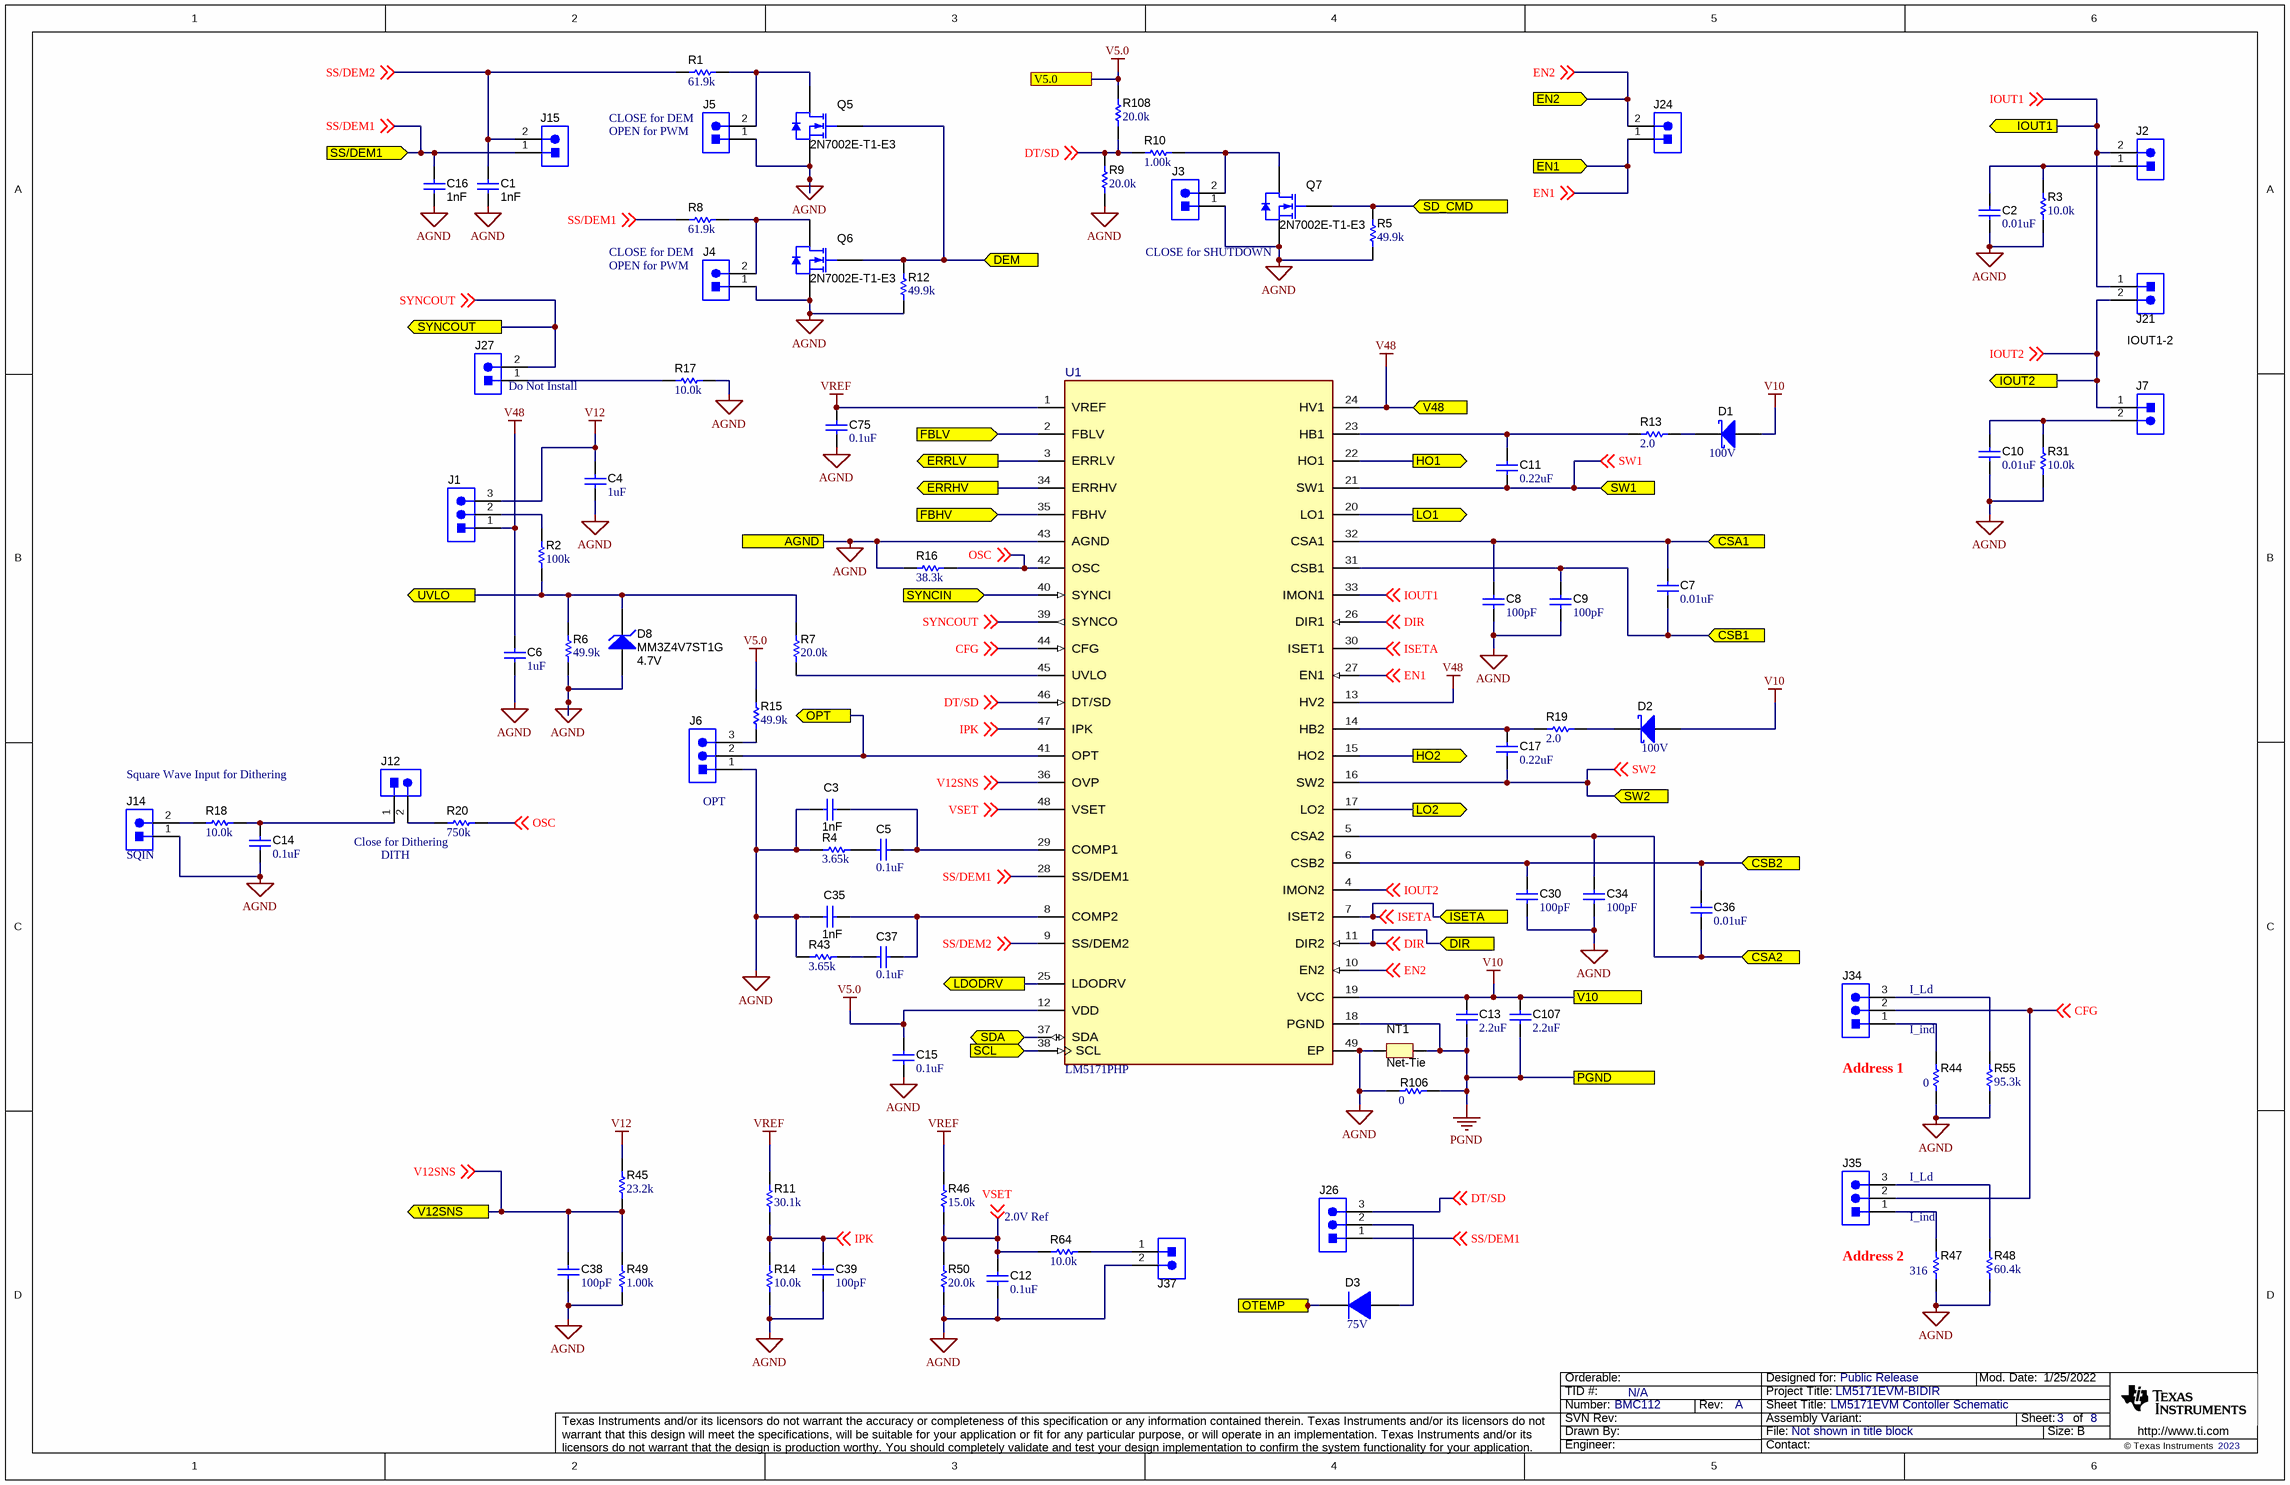
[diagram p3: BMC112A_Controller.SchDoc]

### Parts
C1  Cap_F: 1nF  [0603L]  (hidden comment: C0603C102J5RACAUTO)
C2  ValueDisplayed: 0.01uF  [0603L]  (hidden comment: 06031C103KAT2A)
C3  Cap_F: 1nF  [0603L]  (hidden comment: C0603C102J5RACAUTO)
C4  ValueDisplayed: 1uF  [0805L]  (hidden comment: C2012X7S2A105K125AB)
C5  ValueDisplayed: 0.1uF  [0603L]  (hidden comment: GRM188R72A104KA35D)
C6  ValueDisplayed: 1uF  [0805L]  (hidden comment: C2012X7S2A105K125AB)
C7  ValueDisplayed: 0.01uF  [0603L]  (hidden comment: 06031C103KAT2A)
C8  ValueDisplayed: 100pF  [0603L]  (hidden comment: C0603C101J5GACTU)
C9  ValueDisplayed: 100pF  [0603L]  (hidden comment: C0603C101J5GACTU)
C10  ValueDisplayed: 0.01uF  [0603L]  (hidden comment: 06031C103KAT2A)
C11  ValueDisplayed: 0.22uF  [0603L]  (hidden comment: C1608X7R1H224K080AB)
C12  ValueDisplayed: 0.1uF  [0603L]  (hidden comment: GRM188R72A104KA35D)
C13  ValueDisplayed: 2.2uF  [0805L]  (hidden comment: C2012X7R1C225K125AB)
C14  ValueDisplayed: 0.1uF  [0603L]  (hidden comment: GRM188R72A104KA35D)
C15  ValueDisplayed: 0.1uF  [0603L]  (hidden comment: GRM188R72A104KA35D)
C16  Cap_F: 1nF  [0603L]  (hidden comment: C0603C102J5RACAUTO)
C17  ValueDisplayed: 0.22uF  [0603L]  (hidden comment: C1608X7R1H224K080AB)
C30  ValueDisplayed: 100pF  [0603L]  (hidden comment: C0603C101J5GACTU)
C34  ValueDisplayed: 100pF  [0603L]  (hidden comment: C0603C101J5GACTU)
C35  Cap_F: 1nF  [0603L]  (hidden comment: C0603C102J5RACAUTO)
C36  ValueDisplayed: 0.01uF  [0603L]  (hidden comment: 06031C103KAT2A)
C37  ValueDisplayed: 0.1uF  [0603L]  (hidden comment: GRM188R72A104KA35D)
C38  ValueDisplayed: 100pF  [0603L]  (hidden comment: C0603C101J5GACTU)
C39  ValueDisplayed: 100pF  [0603L]  (hidden comment: C0603C101J5GACTU)
C75  ValueDisplayed: 0.1uF  [0603L]  (hidden comment: GRM188R72A104KA35D)
C107  ValueDisplayed: 2.2uF  [0805L]  (hidden comment: C2012X7R1C225K125AB)
D1  value 100V  [SOD-123W]  (hidden comment: PMEG10010ELRX)
D2  value 100V  [SOD-123W]  (hidden comment: PMEG10010ELRX)
D3  value 75V  [SOD-523]  (hidden comment: 1N4148X-TP)
D8  MM3Z4V7ST1G  value 4.7V  [SOD-323]
J1  61300311121  [WURTH_61300311121]  (value not drawn)
J2  61300211121  [WURTH_61300211121]  (value not drawn)
J3  61300211121  [WURTH_61300211121]  (value not drawn)
J4  61300211121  [WURTH_61300211121]  (value not drawn)
J5  61300211121  [WURTH_61300211121]  (value not drawn)
J6  61300311121  [WURTH_61300311121]  (value not drawn)
J7  61300211121  [WURTH_61300211121]  (value not drawn)
J12  61300211121  [WURTH_61300211121]  (value not drawn)
J14  61300211121  [WURTH_61300211121]  (value not drawn)
J15  61300211121  [WURTH_61300211121]  (value not drawn)
J21  61300211121  [WURTH_61300211121]  (value not drawn)
J24  61300211121  [WURTH_61300211121]  (value not drawn)
J26  61300311121  [WURTH_61300311121]  (value not drawn)
J27  61300211121  [WURTH_61300211121]  (value not drawn)
J34  61300311121  [WURTH_61300311121]  (value not drawn)
J35  61300311121  [WURTH_61300311121]  (value not drawn)
J37  61300211121  [WURTH_61300211121]  (value not drawn)
NT1  Net-Tie  [Net-Tie_10mil]  (net tie, no BOM)
Q5  2N7002E-T1-E3  [SOT-23]
Q6  2N7002E-T1-E3  [SOT-23]
Q7  2N7002E-T1-E3  [SOT-23]
R1  ValueDisplayed: 61.9k  [0603L]  (hidden comment: CRCW060361K9FKEA)
R2  ValueDisplayed: 100k  [0805L]  (hidden comment: CRCW0805100KFKEA)
R3  ValueDisplayed: 10.0k  [0603L]  (hidden comment: CRCW060310K0FKEA)
R4  ValueDisplayed: 3.65k  [0603L]  (hidden comment: RC0603FR-073K65L)
R5  ValueDisplayed: 49.9k  [0603L]  (hidden comment: CRCW060349K9FKEA)
R6  ValueDisplayed: 49.9k  [0603L]  (hidden comment: CRCW060349K9FKEA)
R7  ValueDisplayed: 20.0k  [0603L]  (hidden comment: CRCW060320K0FKEA)
R8  ValueDisplayed: 61.9k  [0603L]  (hidden comment: CRCW060361K9FKEA)
R9  ValueDisplayed: 20.0k  [0603S]  (hidden comment: CRCW060320K0FKEA)
R10  ValueDisplayed: 1.00k  [0603L]  (hidden comment: CRCW06031K00FKEA)
R11  ValueDisplayed: 30.1k  [0603L]  (hidden comment: CRCW060330K1FKEA)
R12  ValueDisplayed: 49.9k  [0603L]  (hidden comment: CRCW060349K9FKEA)
R13  ValueDisplayed: 2.0  [0805L]  (hidden comment: CRCW08052R00JNEA)
R14  ValueDisplayed: 10.0k  [0603L]  (hidden comment: CRCW060310K0FKEA)
R15  ValueDisplayed: 49.9k  [0603L]  (hidden comment: CRCW060349K9FKEA)
R16  ValueDisplayed: 38.3k  [0603L]  (hidden comment: CRCW060338K3FKEA)
R17  ValueDisplayed: 10.0k  [0603L]  (hidden comment: CRCW060310K0FKEA)
R18  ValueDisplayed: 10.0k  [0603L]  (hidden comment: CRCW060310K0FKEA)
R19  ValueDisplayed: 2.0  [0805L]  (hidden comment: CRCW08052R00JNEA)
R20  ValueDisplayed: 750k  [0603L]  (hidden comment: CRCW0603750KFKEA)
R31  ValueDisplayed: 10.0k  [0603L]  (hidden comment: CRCW060310K0FKEA)
R43  ValueDisplayed: 3.65k  [0603L]  (hidden comment: RC0603FR-073K65L)
R44  ValueDisplayed: 0  [0603L]  (hidden comment: ERJ-3GEY0R00V)
R45  ValueDisplayed: 23.2k  [0603L]  (hidden comment: CRCW060323K2FKEA)
R46  ValueDisplayed: 15.0k  [0603L]  (hidden comment: CRCW060315K0FKEA)
R47  ValueDisplayed: 316  [0603L]  (hidden comment: CRCW0603316RFKEA)
R48  ValueDisplayed: 60.4k  [0603L]  (hidden comment: CRCW060360K4FKEA)
R49  ValueDisplayed: 1.00k  [0603L]  (hidden comment: CRCW06031K00FKEA)
R50  ValueDisplayed: 20.0k  [0603L]  (hidden comment: CRCW060320K0FKEA)
R55  ValueDisplayed: 95.3k  [0603L]  (hidden comment: CRCW060395K3FKEA)
R64  ValueDisplayed: 10.0k  [0603S]  (hidden comment: CRCW060310K0FKEA)
R106  ValueDisplayed: 0  [0603L]  (hidden comment: ERJ-3GEY0R00V)
R108  ValueDisplayed: 20.0k  [0603S]  (hidden comment: CRCW060320K0FKEA)
U1  LM5171PHP  [PHP0048E-MFG]

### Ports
AGND, CSA1 (in), CSA2 (in), CSB1 (in), CSB2 (in), DEM (in), DIR (in), EN1 (in), EN2 (in), ERRHV (out), ERRLV (out), FBHV (in), FBLV (in), HO1 (out), HO2 (out), IOUT1 (out), IOUT2 (out), ISETA (in), LDODRV (out), LO1 (out), LO2 (out), OPT (out), OTEMP (out), PGND, SCL (in), SD_CMD (in), SDA (bidir), SS/DEM1 (in), SW1 (in), SW2 (in), SYNCIN (in), SYNCOUT (out), UVLO (out), V5.0, V10, V12SNS (out), V48 (in)

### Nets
AGND: C1.2 C2.1 C3.1 C4.2 C6.2 C8.2 C9.2 C10.2 C12.2 C14.2 C15.2 C16.2 C30.2 C34.2 C35.1 C38.2 C39.2 C75.2 D8.2(A) J3.1 J4.1 J5.1 J6.1 J14.1 J37.2 NT1.1 Q5.2(S) Q6.2(S) Q7.2(S) R3.1 R4.2 R5.1 R6.1 R9.1 R12.1 R14.1 R16.1 R17.2 R31.1 R43.1 R44.1 R47.1 R48.1 R49.1 R50.1 R55.1 R106.2 U1.43(AGND) U1.49(EP) ; port AGND
PGND: C13.2 C107.2 NT1.2 R106.1 U1.18(PGND) ; port PGND
V5.0: C15.1 R15.2 R108.2 U1.12(VDD) ; port V5.0
V10: C13.1 C107.1 D1.2(A) D2.2(A) U1.19(VCC) ; port V10
V12: C4.1 J1.3 R45.2
V48: C6.1 J1.1 U1.13(HV2) U1.24(HV1) ; port V48
VREF: C75.1 R11.2 R46.1 U1.1(VREF)
CFG: J34.2 J35.2 U1.44(CFG) ; off-sheet CFG
CSA1: C7.1 C8.1 U1.32(CSA1) ; port CSA1
CSA2: C34.1 C36.2 U1.5(CSA2) ; port CSA2
CSB1: C7.2 C9.1 U1.31(CSB1) ; port CSB1
CSB2: C30.1 C36.1 U1.6(CSB2) ; port CSB2
DEM: Q5.1(G) Q6.1(G) R12.2 ; port DEM
DIR: U1.11(DIR2) U1.26(DIR1) ; off-sheet DIR, port DIR
DT/SD: J26.3 R9.2 R10.2 R108.1 U1.46(DT/SD) ; off-sheet DT/SD
EN1: J24.1 U1.27(EN1) ; off-sheet EN1, port EN1
EN2: J24.2 U1.10(EN2) ; off-sheet EN2, port EN2
ERRHV: U1.34(ERRHV) ; port ERRHV
ERRLV: U1.3(ERRLV) ; port ERRLV
FBHV: U1.35(FBHV) ; port FBHV
FBLV: U1.2(FBLV) ; port FBLV
HO1: U1.22(HO1) ; port HO1
HO2: U1.15(HO2) ; port HO2
IOUT1: J2.2 J21.1 U1.33(IMON1) ; off-sheet IOUT1, port IOUT1
IOUT2: J7.1 J21.2 U1.4(IMON2) ; off-sheet IOUT2, port IOUT2
IPK: C39.1 R11.1 R14.2 U1.47(IPK) ; off-sheet IPK
ISETA: U1.7(ISET2) U1.30(ISET1) ; off-sheet ISETA, port ISETA
LDODRV: U1.25(LDODRV) ; port LDODRV
LO1: U1.20(LO1) ; port LO1
LO2: U1.17(LO2) ; port LO2
OPT: J6.2 U1.41(OPT) ; port OPT
OSC: R16.2 R20.1 U1.42(OSC) ; off-sheet OSC
OTEMP: D3.1(K) ; port OTEMP
SCL: U1.38(SCL) ; port SCL
SD_CMD: Q7.1(G) R5.2 ; port SD_CMD
SDA: U1.37(SDA) ; port SDA
SS/DEM1: C16.1 J15.1 J26.1 R8.2 U1.28(SS/DEM1) ; off-sheet SS/DEM1, port SS/DEM1
SS/DEM2: C1.1 J15.2 R1.2 U1.9(SS/DEM2) ; off-sheet SS/DEM2
SW1: C11.2 U1.21(SW1) ; off-sheet SW1, port SW1
SW2: C17.2 U1.16(SW2) ; off-sheet SW2, port SW2
SYNCIN: U1.40(SYNCI) ; port SYNCIN
SYNCOUT: J27.2 U1.39(SYNCO) ; off-sheet SYNCOUT, port SYNCOUT
UVLO: D8.1(K) R2.1 R6.2 R7.2 ; port UVLO
V12SNS: C38.1 R45.1 R49.2 U1.36(OVP) ; off-sheet V12SNS, port V12SNS
VSET: C12.1 R46.2 R50.2 R64.2 U1.48(VSET) ; off-sheet VSET
NetC2_2: C2.2 J2.1 R3.2
NetC3_2: C3.2 C5.2 U1.29(COMP1)
NetC5_1: C5.1 R4.1
NetC10_1: C10.1 J7.2 R31.2
NetC11_1: C11.1 R13.1 U1.23(HB1)
NetC14_1: C14.1 J12.1 R18.2
NetC17_1: C17.1 R19.1 U1.14(HB2)
NetC35_2: C35.2 C37.1 U1.8(COMP2)
NetC37_2: C37.2 R43.2
NetD1_1: D1.1(K) R13.2
NetD2_1: D2.1(K) R19.2
NetD3_2: D3.2(A) J26.2
NetJ1_2: J1.2 R2.2
NetJ3_2: J3.2 Q7.3(D) R10.1
NetJ4_2: J4.2 Q6.3(D) R8.1
NetJ5_2: J5.2 Q5.3(D) R1.1
NetJ6_3: J6.3 R15.1
NetJ12_2: J12.2 R20.2
NetJ14_2: J14.2 R18.1
NetJ27_1: J27.1 R17.1
NetJ34_1: J34.1 R44.2
NetJ34_3: J34.3 R55.2
NetJ35_1: J35.1 R47.2
NetJ35_3: J35.3 R48.2
NetJ37_1: J37.1 R64.1
NetR7_1: R7.1 U1.45(UVLO)

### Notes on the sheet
- CLOSE for DEM
- OPEN for PWM
- CLOSE for SHUTDOWN
- (near J21) IOUT1-2
- (near J27) Do Not Install
- Square Wave Input for Dithering
- (near J6) OPT
- (near J14) SQIN
- (near R20) Close for Dithering
- DITH
- (near J34) I_Ld
- I_ind
- Address 1
- (near R64) 2.0V Ref
- (near J35) I_Ld
- Address 2

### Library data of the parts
C1 C3 C16 C35 = CMP-0006844-4: as C79 on sheet BMC112A_Bias
C2 C7 C10 C36 = CMP-0006727-4: CAP, CERM, 0.01 uF, 100 V, +/- 10%, X7R, 0603; Manufacturer: AVX; Polarized: N; Value: 0.01uF; U/M: EA; Cap_F: 10nF; ESR_ohm: 98m; Value1: 0.098 ohm; VDC_V: 100V; TaMin_C: -55°C; TaMax_C: 125°C; Cap_Case: 0603; AEC Category: Q200; SizeArea_mm2: 1.28; SizeAreaWB_mm2: 4.68; SizeX_mm: 1.6; SizeY_mm: 0.8; SizeZ_mm: 1
C4 C6 = CMP-0007891-2: CAP, CERM, 1 uF, 100 V, +/- 10%, X7S, 0805; Manufacturer: TDK; Polarized: N; Value: 1uF; U/M: EA; Cap_F: 1µF; ESR_ohm: 8.255m; Value1: 0.008255 ohm; VDC_V: 100V; IRMS_A: 2.2744A; TaMin_C: -55°C; TaMax_C: 125°C; Cap_Case: 0805; AEC Category: Q200; SizeArea_mm2: 2.5; SizeAreaWB_mm2: 6.75; SizeX_mm: 2; SizeY_mm: 1.25; SizeZ_mm: 1.45
C5 C12 C14 C15 C37 C75 = CMP-0007469-4: as C89 on sheet BMC112A_OVP
C8 C9 C30 C34 C38 C39 = CMP-0006841-4: as C95 on sheet BMC112A_OVP
C11 C17 = CMP-0007047-4: CAP, CERM, 0.22 uF, 50 V, +/- 10%, X7R, 0603; Manufacturer: TDK; Polarized: N; Value: 0.22uF; U/M: EA; Cap_F: 220nF; ESR_ohm: 21.699m; Value1: 0.021699 ohm; VDC_V: 50V; IRMS_A: 1.125A; TaMin_C: -55°C; TaMax_C: 125°C; Cap_Case: 0603; AEC Category: Q200; SizeArea_mm2: 1.28; SizeAreaWB_mm2: 4.68; SizeX_mm: 1.6; SizeY_mm: 0.8; SizeZ_mm: 1
C13 C107 = CMP-0007867-2: as C80 on sheet BMC112A_Bias
D1 D2 = CMP-0028782-2: Diode, Schottky, 100 V, 1 A, AEC-Q101, SOD-123W; Manufacturer: Nexperia; Vf_V: 770mV; Value1: 1A; Value2: 0.77V; TJmax_C: 175°C; AEC Category: Q101; AEC Qualified: Y; Green_Lifecycle: Not Set; Green_REACh: Incomplete; SizeArea_mm2: 5.95; SizeAreaWB_mm2: 12.15; SizeX_mm: 3.5; SizeY_mm: 1.7; SizeZ_mm: 1
D3 = CMP-0076957-3: Diode, Switching, 75 V, 0.3 A, SOD-523; Manufacturer: Micro Commercial Components; Vf_V: 1.25V; Value1: 0.3A; Io_A: 300mA; TJmax_C: 150°C; AEC Category: Q101; Green_Lifecycle: Not Set; Green_REACh: Incomplete; SizeArea_mm2: 1.53; SizeAreaWB_mm2: 5.13; SizeX_mm: 1.7; SizeY_mm: 0.9; SizeZ_mm: 0.65
D8 = CMP-0085737-1: Diode, Zener, 4.7 V, 300 mW, SOD-323; Manufacturer: ON Semiconductor; SizeArea_mm2: 3.645; SizeZ_mm: 1; SizeAreaWB_mm2: 8.695; RJA_CperW: 416; SizeY_mm: 1.35; Power_W: 300mW; AEC Qualified: N; SizeX_mm: 2.7; AEC Category: Q101; Value1: 0.3W
J1 = CMP-0054796-4: Header, 2.54 mm, 3x1, Gold, TH; Manufacturer: Wurth Elektronik; Green_Lifecycle: Active; Green_REACh: Passed; CT: FALSE; CNHeader: TRUE
J2-J5 J7 J12 J14 J15 J21 J24 J27 J37 = CMP-0054794-2: as J42 on sheet BMC112A_OVP
J6 J26 J34 J35 = CMP-0054796-4: Header, 2.54 mm, 3x1, Gold, TH; Manufacturer: Wurth Elektronik; Green_Lifecycle: Active; Green_REACh: Passed; CNHeader: TRUE; CT: FALSE
NT1 = CMP-0078142-6: Single point connection between nets.
Q5-Q7 = CMP-0000771-1: MOSFET, N-CH, 60 V, 0.24 A, SOT-23; Manufacturer: Vishay-Siliconix; Alternate Manufacturer: None; U/M: EA; ChType: N; Value: 60V; Value1: 1; Rdson45_ohm: 1.8; Value2: 0.4 nC; QgTyp_nC: 0.4; Vgs_V: 20V; IdsMax_A: 240mA; AEC Category: Q101; SizeArea_mm2: 7.5; SizeAreaWB_mm2: 14; SizeX_mm: 2.5; SizeY_mm: 3; SizeZ_mm: 1.1
R1 R8 = CMP-0022536-4: RES, 61.9 k, 1%, 0.1 W, AEC-Q200 Grade 0, 0603; Manufacturer: Vishay-Dale; Value: 61.9k; Value_Code: 61k9; Power_W: 100mW; Value2: 0.1W; VDC_V: 75V; TempCo: 100 ppm/C; EIA_Code: E96; SizeX_mm: 1.6; SizeY_mm: 0.8; SizeZ_mm: 1; SizeArea_mm2: 1.28; AEC Qualified: Y; AEC Category: Q200; AEC Grade: 0
R2 = CMP-0020834-3: as R88 on sheet BMC112A_OVP
R3 R14 R17 R18 R31 R64 = CMP-0021998-4: RES, 10.0 k, 1%, 0.1 W, AEC-Q200 Grade 0, 0603; Manufacturer: Vishay-Dale; Value: 10.0k; Res_ohm: 10k; Value_Code: 10k0; Power_W: 100mW; Value2: 0.1W; VDC_V: 75V; TempCo: 100 ppm/C; EIA_Code: E96; AEC Category: Q200; AEC Grade: 0; AEC Qualified: Y; SizeArea_mm2: 1.28; SizeX_mm: 1.6; SizeY_mm: 0.8; SizeZ_mm: 1
R4 R43 = CMP-0023085-5: RES, 3.65 k, 1%, 0.1 W, 0603; Manufacturer: Yageo; Value: 3.65k; Value_Code: 3k65; Power_W: 100mW; Value2: 0.1W; VDC_V: 75V; TempCo: 100 ppm/C; EIA_Code: E96; AEC Category: Q200; AEC Qualified: N; SizeArea_mm2: 1.28; SizeX_mm: 1.6; SizeY_mm: 0.8; SizeZ_mm: 1; SizeAreaWB_mm2: 4.68
R5 R6 R12 R15 = CMP-0022447-4: RES, 49.9 k, 1%, 0.1 W, AEC-Q200 Grade 0, 0603; Manufacturer: Vishay-Dale; Value: 49.9k; Value_Code: 49k9; Power_W: 100mW; Value2: 0.1W; VDC_V: 75V; TempCo: 100 ppm/C; EIA_Code: E96; AEC Category: Q200; AEC Grade: 0; AEC Qualified: Y; SizeArea_mm2: 1.28; SizeX_mm: 1.6; SizeY_mm: 0.8; SizeZ_mm: 1
R7 = CMP-0022204-4: RES, 20.0 k, 1%, 0.1 W, AEC-Q200 Grade 0, 0603; Manufacturer: Vishay-Dale; Value: 20.0k; Res_ohm: 20k; Value_Code: 20k0; Power_W: 100mW; Value2: 0.1W; VDC_V: 75V; TempCo: 100 ppm/C; EIA_Code: E96; AEC Category: Q200; AEC Grade: 0; AEC Qualified: Y; SizeArea_mm2: 1.28; SizeX_mm: 1.6; SizeY_mm: 0.8; SizeZ_mm: 1
R9 R108 = CMP-0022204-4: RES, 20.0 k, 1%, 0.1 W, AEC-Q200 Grade 0, 0603; Manufacturer: Vishay-Dale; Power_W: 100mW; TempCo: 100 ppm/C; Value_Code: 20k0; Value: 20.0k; EIA_Code: E96; Res_ohm: 20k; SizeX_mm: 1.6; SizeY_mm: 0.8; SizeZ_mm: 1; Value2: 0.1W; SizeArea_mm2: 1.28; AEC Qualified: Y; VDC_V: 75V; AEC Category: Q200; AEC Grade: 0
R10 R49 = CMP-0022109-5: RES, 1.00 k, 1%, 0.1 W, AEC-Q200 Grade 0, 0603; Manufacturer: Vishay-Dale; Value: 1.00k; Res_ohm: 1k; Value_Code: 1k00; Power_W: 100mW; Value2: 0.1W; VDC_V: 75V; TempCo: 100 ppm/C; EIA_Code: E96; SizeX_mm: 1.6; SizeY_mm: 0.8; SizeZ_mm: 1; SizeArea_mm2: 1.28; AEC Qualified: Y; AEC Category: Q200; AEC Grade: 0
R11 = CMP-0022324-4: RES, 30.1 k, 1%, 0.1 W, AEC-Q200 Grade 0, 0603; Manufacturer: Vishay-Dale; Power_W: 100mW; TempCo: 100 ppm/C; Value_Code: 30k1; Value: 30.1k; EIA_Code: E96; SizeX_mm: 1.6; SizeY_mm: 0.8; SizeZ_mm: 1; Value2: 0.1W; SizeArea_mm2: 1.28; AEC Qualified: Y; VDC_V: 75V; AEC Category: Q200; AEC Grade: 0
R13 R19 = CMP-0020518-3: RES, 2.0, 5%, 0.125 W, AEC-Q200 Grade 0, 0805; Manufacturer: Vishay-Dale; Value: 2.0; Res_ohm: 2; Value_Code: 2R00; Power_W: 125mW; Value2: 0.125W; VDC_V: 150V; TempCo: 200 ppm/C; EIA_Code: E24; AEC Category: Q200; AEC Qualified: Y; AEC Grade: 0; SizeArea_mm2: 2.5; SizeY_mm: 1.25; SizeZ_mm: 1.45
R16 = CMP-0022364-4: RES, 38.3 k, 1%, 0.1 W, AEC-Q200 Grade 0, 0603; Manufacturer: Vishay-Dale; Value: 38.3k; Value_Code: 38k3; Power_W: 100mW; Value2: 0.1W; VDC_V: 75V; TempCo: 100 ppm/C; EIA_Code: E96; SizeArea_mm2: 1.28; SizeX_mm: 1.6; SizeY_mm: 0.8; SizeZ_mm: 1; AEC Category: Q200; AEC Qualified: Y; AEC Grade: 0
R20 = CMP-0022587-4: RES, 750 k, 1%, 0.1 W, AEC-Q200 Grade 0, 0603; Manufacturer: Vishay-Dale; Value: 750k; Power_W: 100mW; Value2: 0.1W; VDC_V: 75V; TempCo: 100 ppm/C; EIA_Code: E96; SizeX_mm: 1.6; SizeY_mm: 0.8; SizeZ_mm: 1; SizeArea_mm2: 1.28; AEC Qualified: Y; AEC Category: Q200; AEC Grade: 0
R44 R106 = CMP-0025874-4: RES, 0, 5%, 0.1 W, AEC-Q200 Grade 0, 0603; Manufacturer: Panasonic; Value: 0; Power_W: 100mW; VDC_V: 50V; SizeZ_mm: 1; AEC Qualified: Y; TempCo: 600 ppm/C; Value_Code: 0000; EIA_Code: E24; SizeX_mm: 1.6; SizeY_mm: 0.8; Value2: 0.1W; SizeArea_mm2: 1.28; AEC Category: Q200; SizeAreaWB_mm2: 4.68
R45 = CMP-0022228-4: RES, 23.2 k, 1%, 0.1 W, AEC-Q200 Grade 0, 0603; Manufacturer: Vishay-Dale; Power_W: 100mW; TempCo: 100 ppm/C; Value_Code: 23k2; Value: 23.2k; EIA_Code: E96; SizeX_mm: 1.6; SizeY_mm: 0.8; SizeZ_mm: 1; Value2: 0.1W; SizeArea_mm2: 1.28; AEC Qualified: Y; VDC_V: 75V; AEC Category: Q200; AEC Grade: 0
R46 = CMP-0022066-4: as R89 on sheet BMC112A_OVP
R47 = CMP-0022329-5: RES, 316, 1%, 0.1 W, AEC-Q200 Grade 0, 0603; Manufacturer: Vishay-Dale; Value: 316; Power_W: 100mW; VDC_V: 75V; SizeZ_mm: 1; AEC Qualified: Y; TempCo: 100 ppm/C; Value_Code: 316R; EIA_Code: E96; SizeX_mm: 1.6; SizeY_mm: 0.8; Value2: 0.1W; SizeArea_mm2: 1.28; AEC Category: Q200; AEC Grade: 0
R48 = CMP-0022532-4: RES, 60.4 k, 1%, 0.1 W, AEC-Q200 Grade 0, 0603; Manufacturer: Vishay-Dale; Value: 60.4k; Value_Code: 60k4; Power_W: 100mW; Value2: 0.1W; VDC_V: 75V; TempCo: 100 ppm/C; EIA_Code: E96; SizeX_mm: 1.6; SizeY_mm: 0.8; SizeZ_mm: 1; SizeArea_mm2: 1.28; AEC Qualified: Y; AEC Category: Q200; AEC Grade: 0
R50 = CMP-0022204-4: as R109 on sheet BMC112A_OVP
R55 = CMP-0022659-4: RES, 95.3 k, 1%, 0.1 W, AEC-Q200 Grade 0, 0603; Manufacturer: Vishay-Dale; Value: 95.3k; Value_Code: 95k3; Power_W: 100mW; Value2: 0.1W; VDC_V: 75V; TempCo: 100 ppm/C; EIA_Code: E96; SizeX_mm: 1.6; SizeY_mm: 0.8; SizeZ_mm: 1; SizeArea_mm2: 1.28; AEC Qualified: Y; AEC Category: Q200; AEC Grade: 0
U1 = CMP-0097493-1: Dual Channel 48V-12V Bidirectional PWM Controller; Manufacturer: Texas Instruments; TaMin_C: -40°C; Standoff Height: 0.05mm; AEC Grade: Grade 1; SizeZ_mm: 1.2mm; AEC Qualified: Yes; TaMax_C: +125°C; Number Of Outputs: 2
